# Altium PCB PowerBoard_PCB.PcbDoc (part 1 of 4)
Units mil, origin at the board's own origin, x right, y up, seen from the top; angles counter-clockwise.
Board outline 9251.97 x 3346.46 mil, 6 copper layers (Top Layer, Signal Layer 1, Signal Layer 2, Signal Layer 3, Signal Layer 4, Bottom Layer), stack 65.8 mil thick; 241 components, 145 nets, 894 pads, 120 vias.
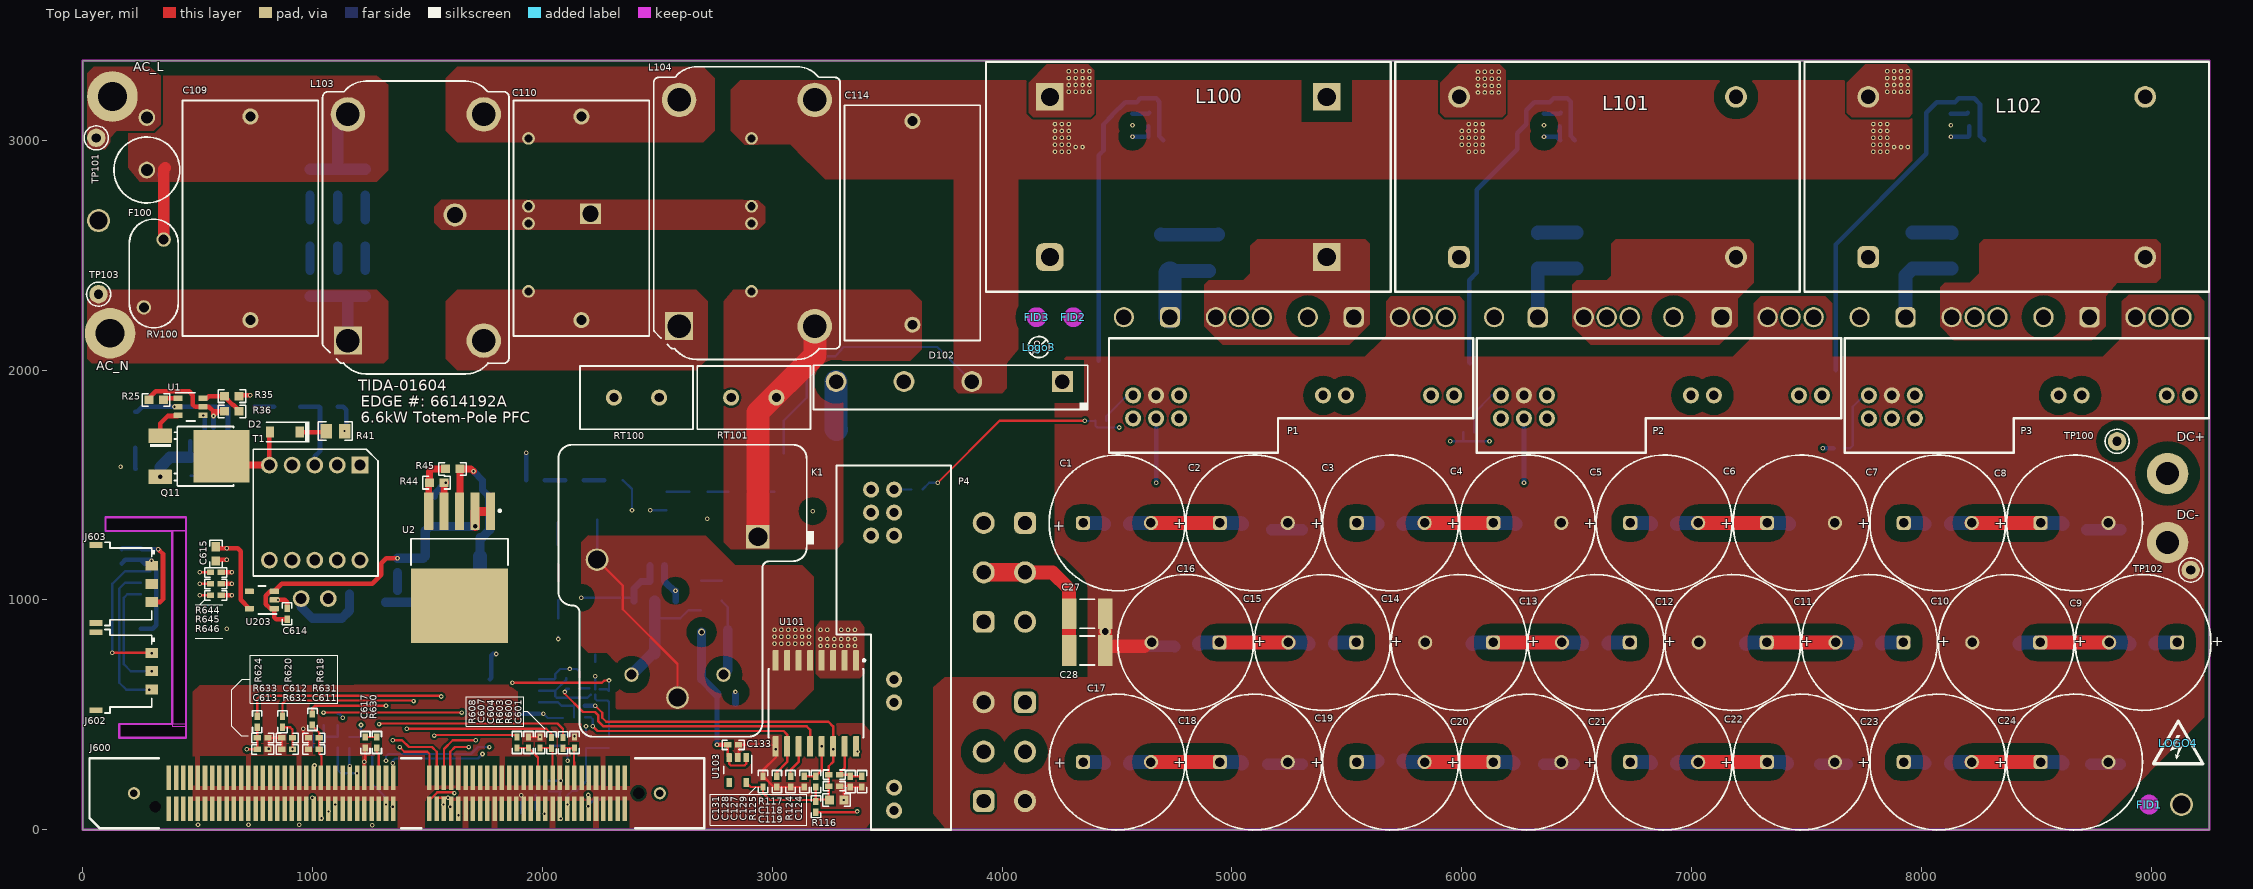
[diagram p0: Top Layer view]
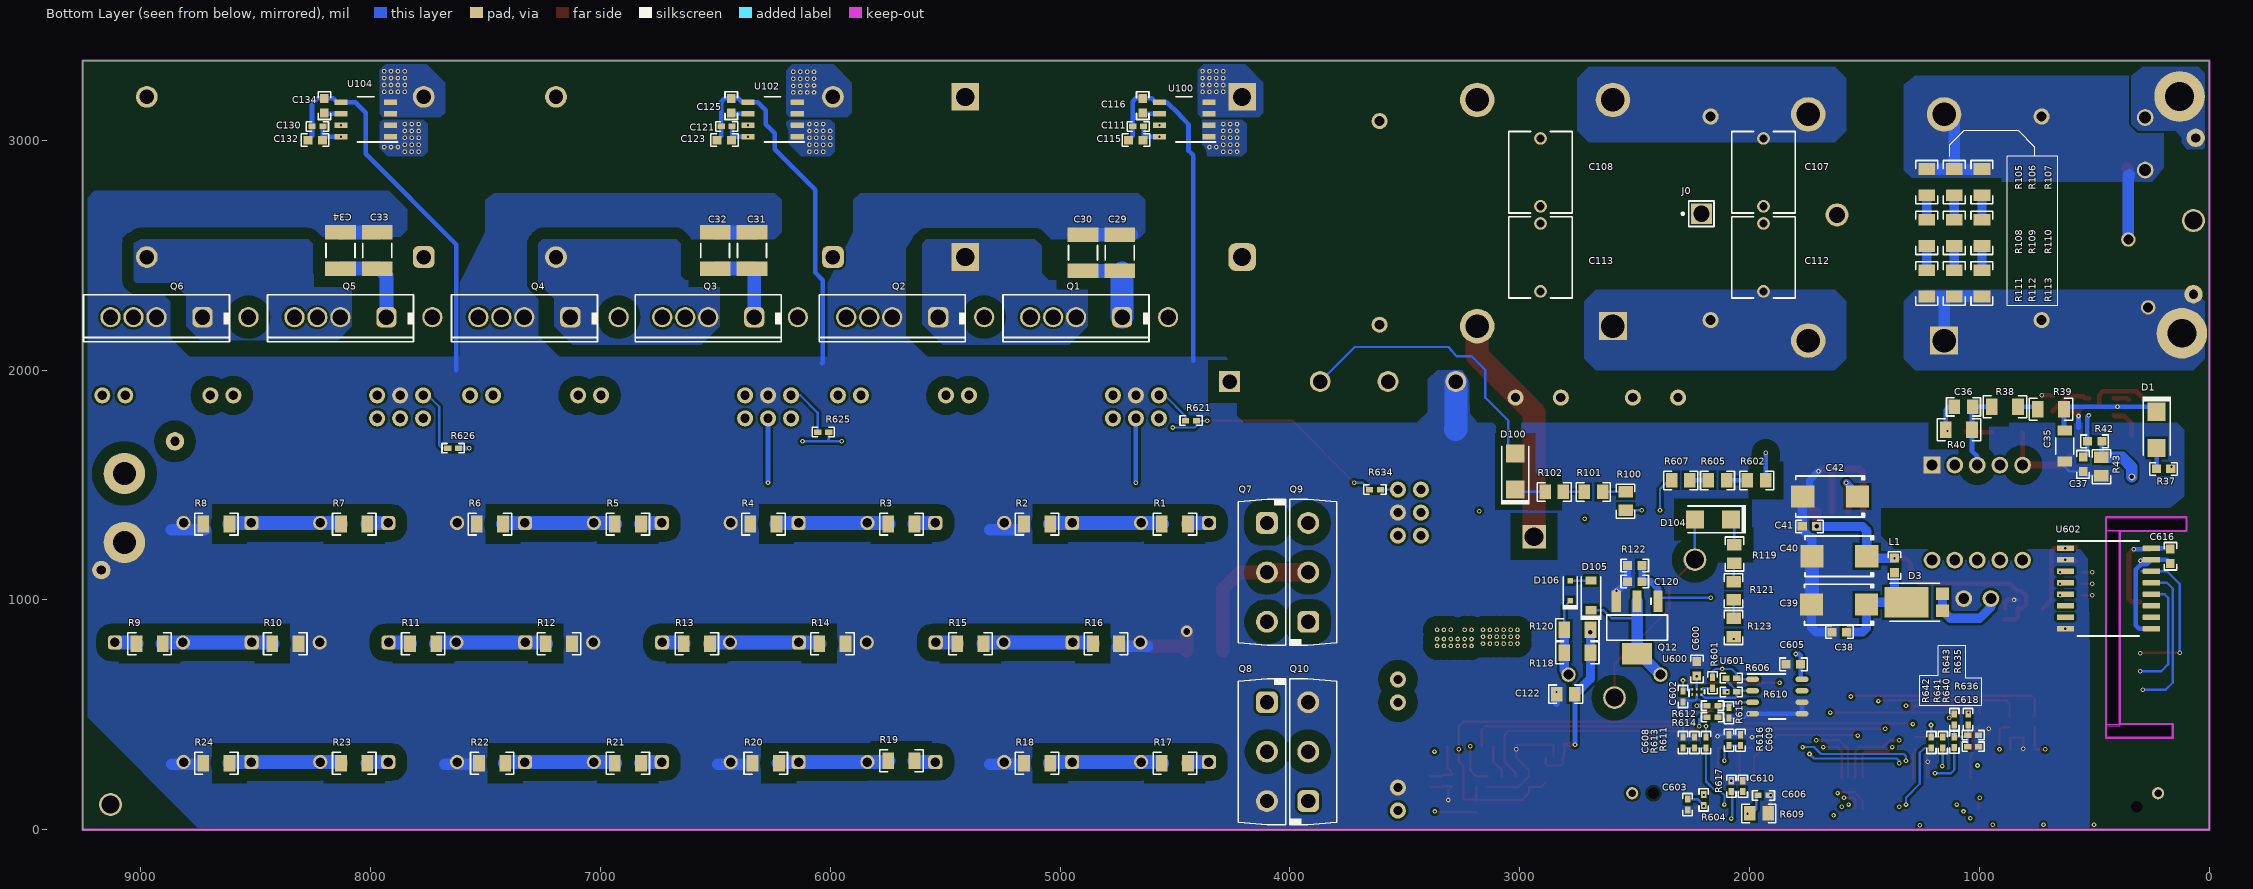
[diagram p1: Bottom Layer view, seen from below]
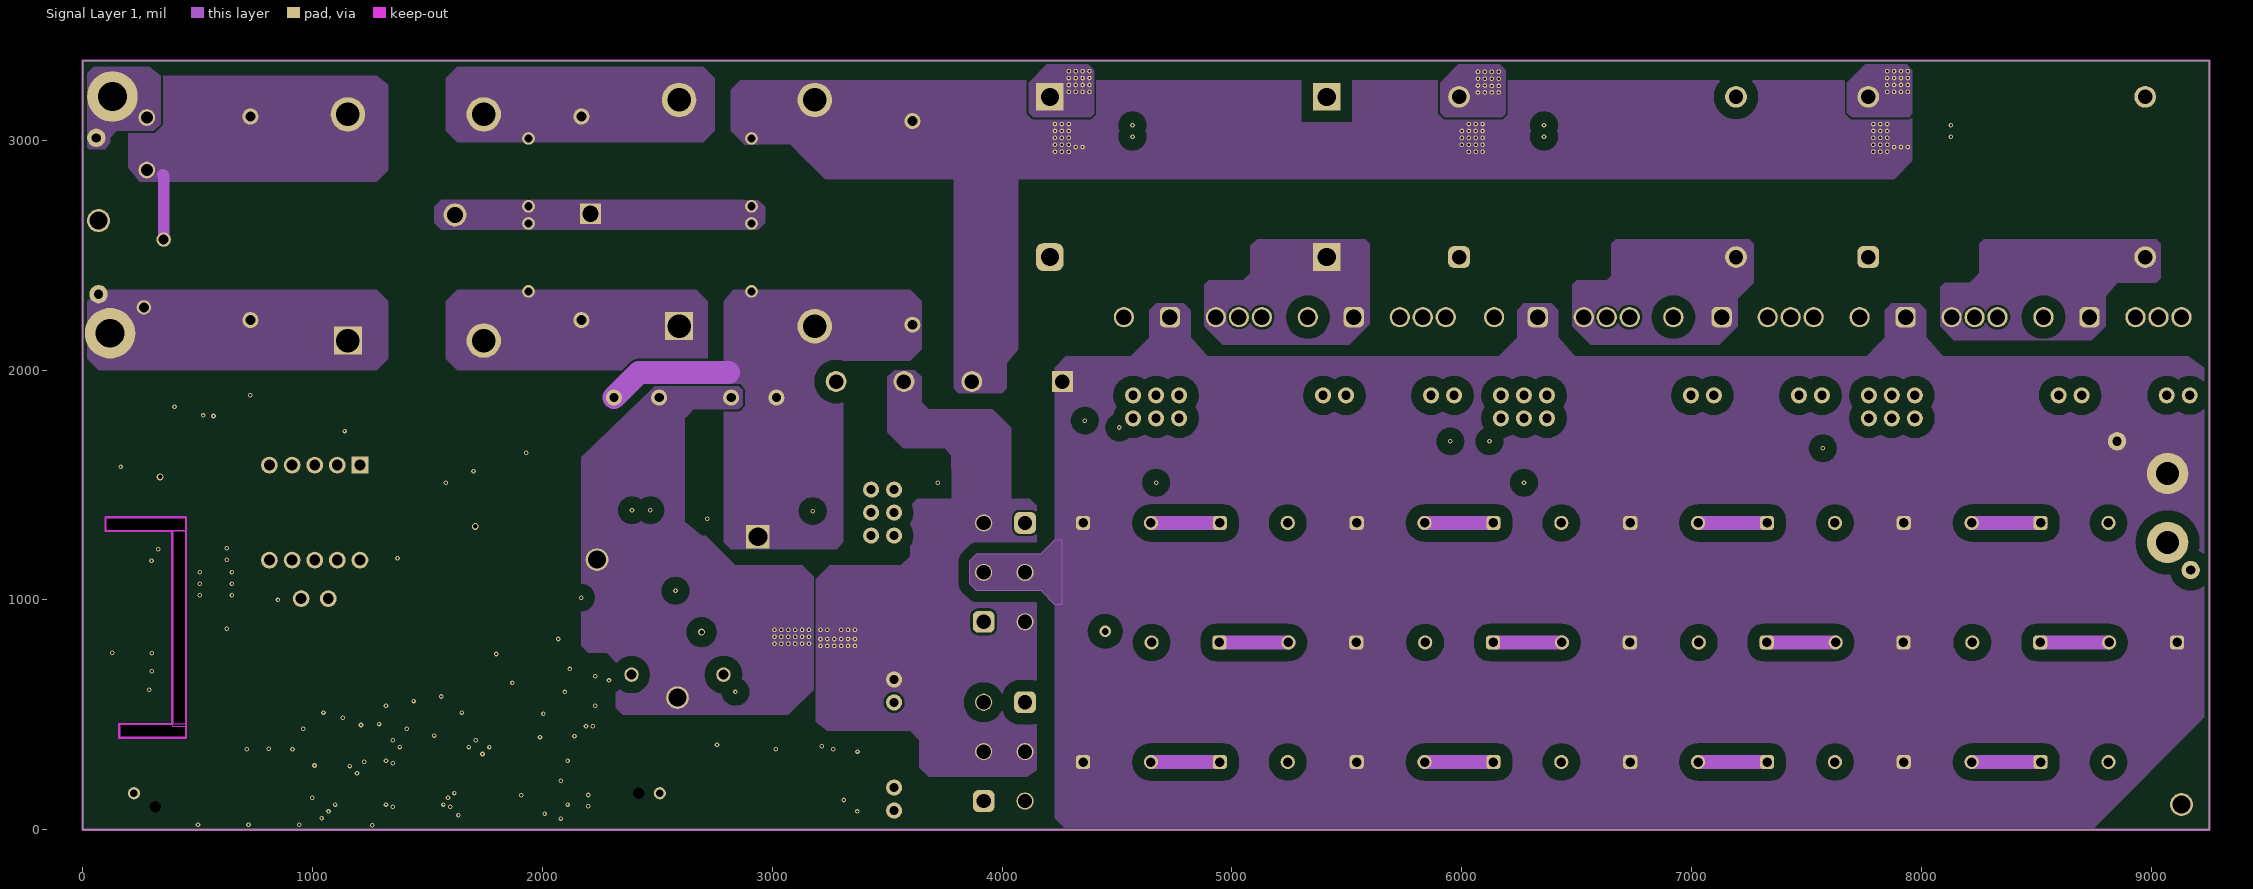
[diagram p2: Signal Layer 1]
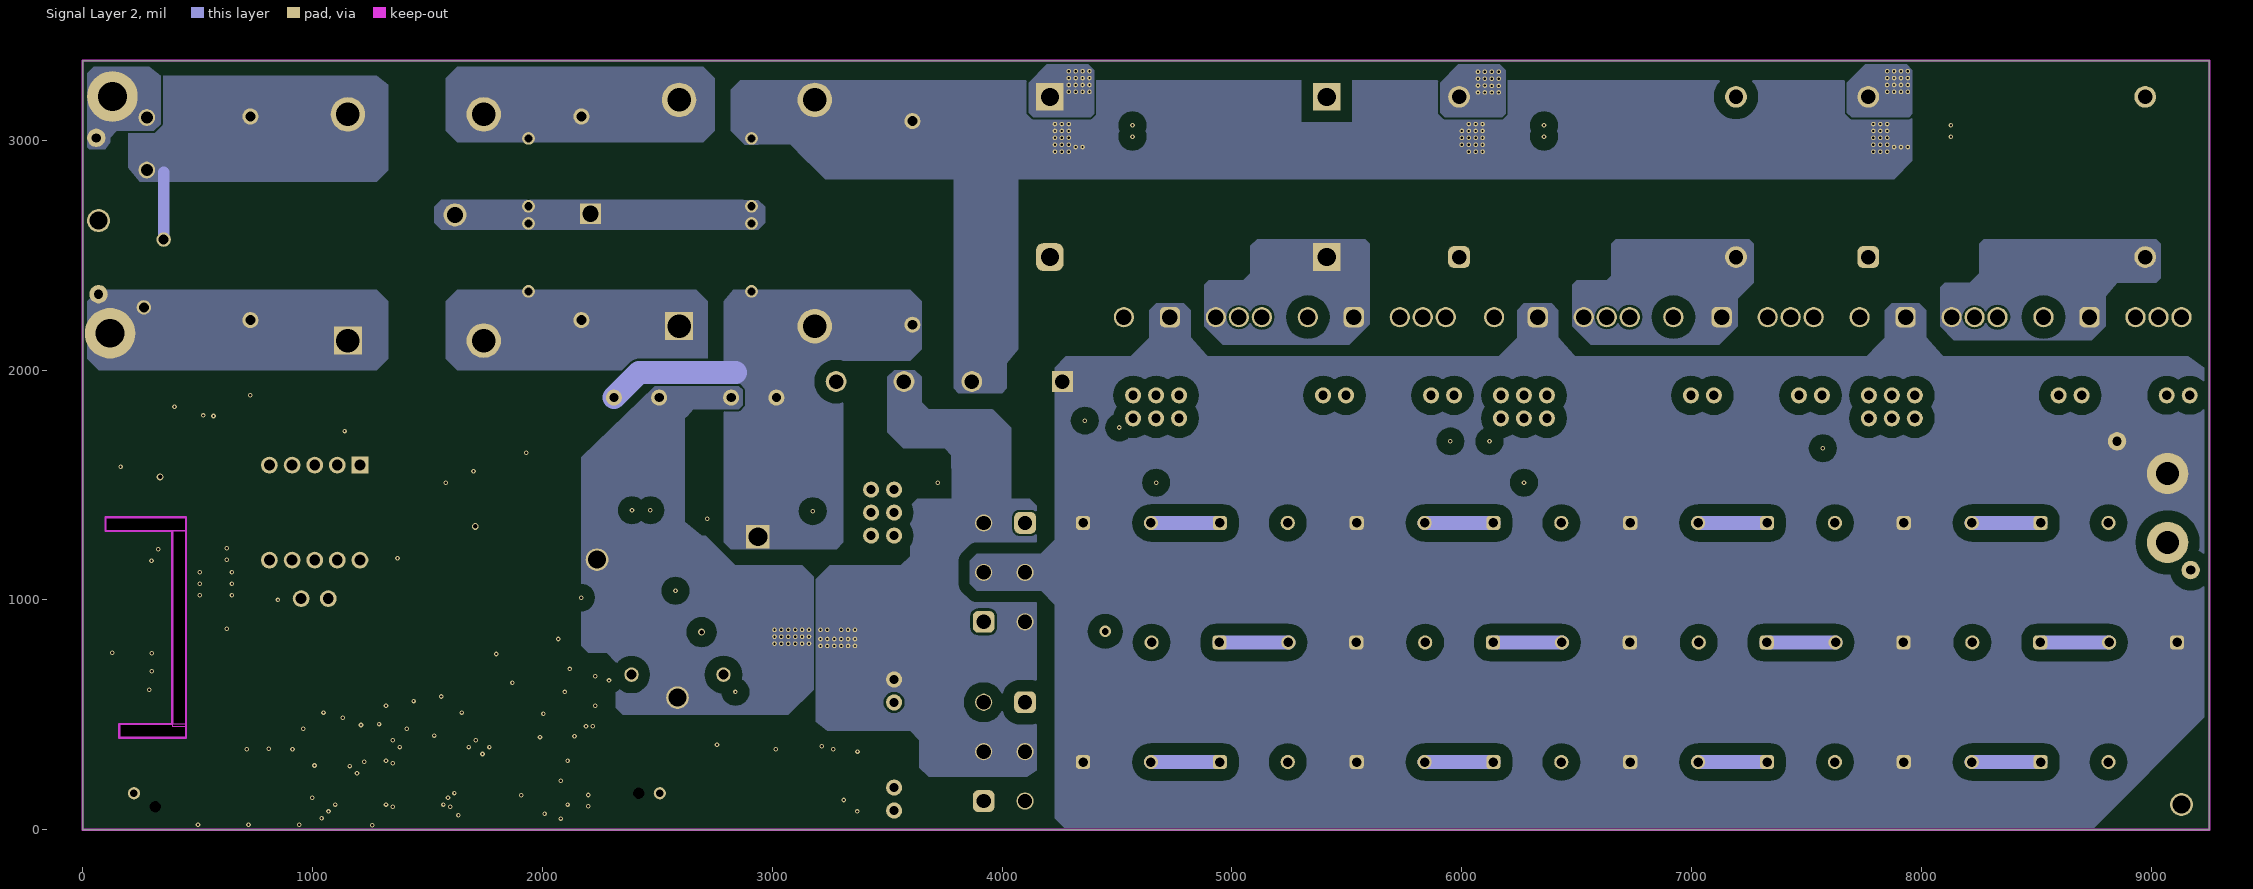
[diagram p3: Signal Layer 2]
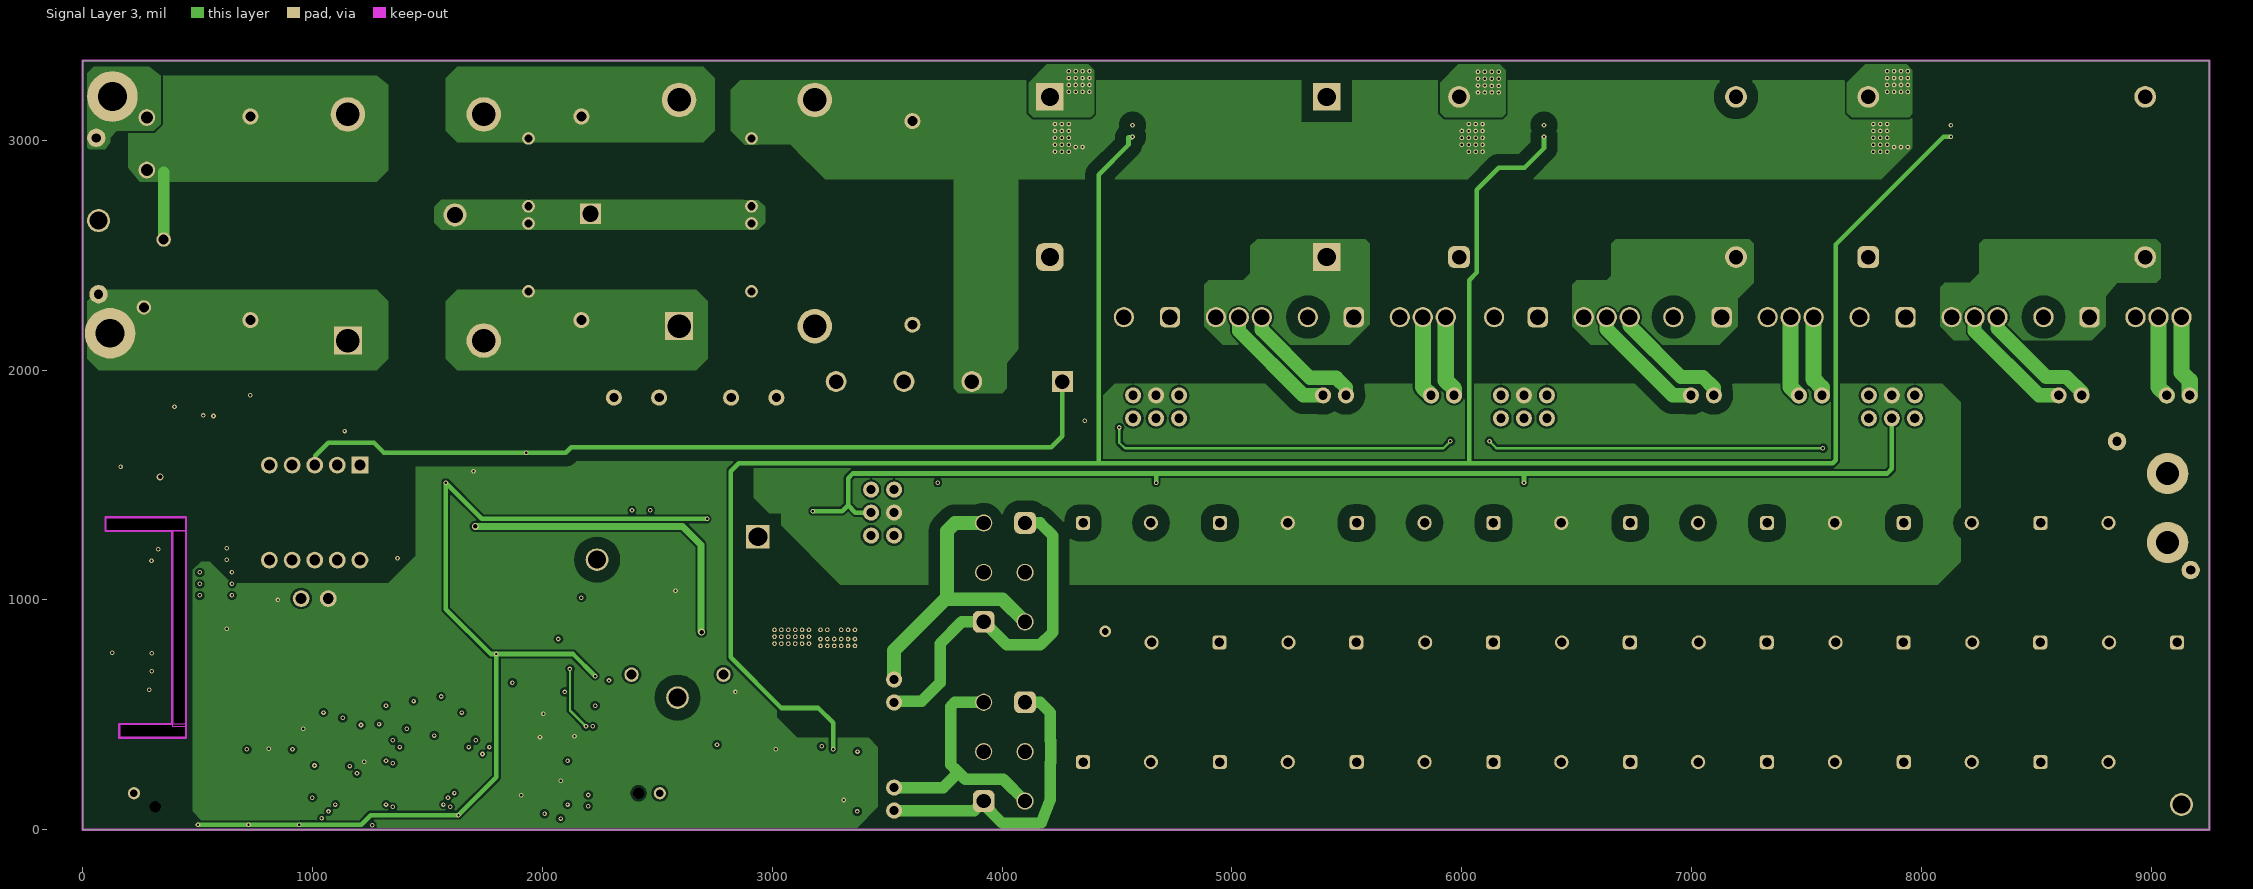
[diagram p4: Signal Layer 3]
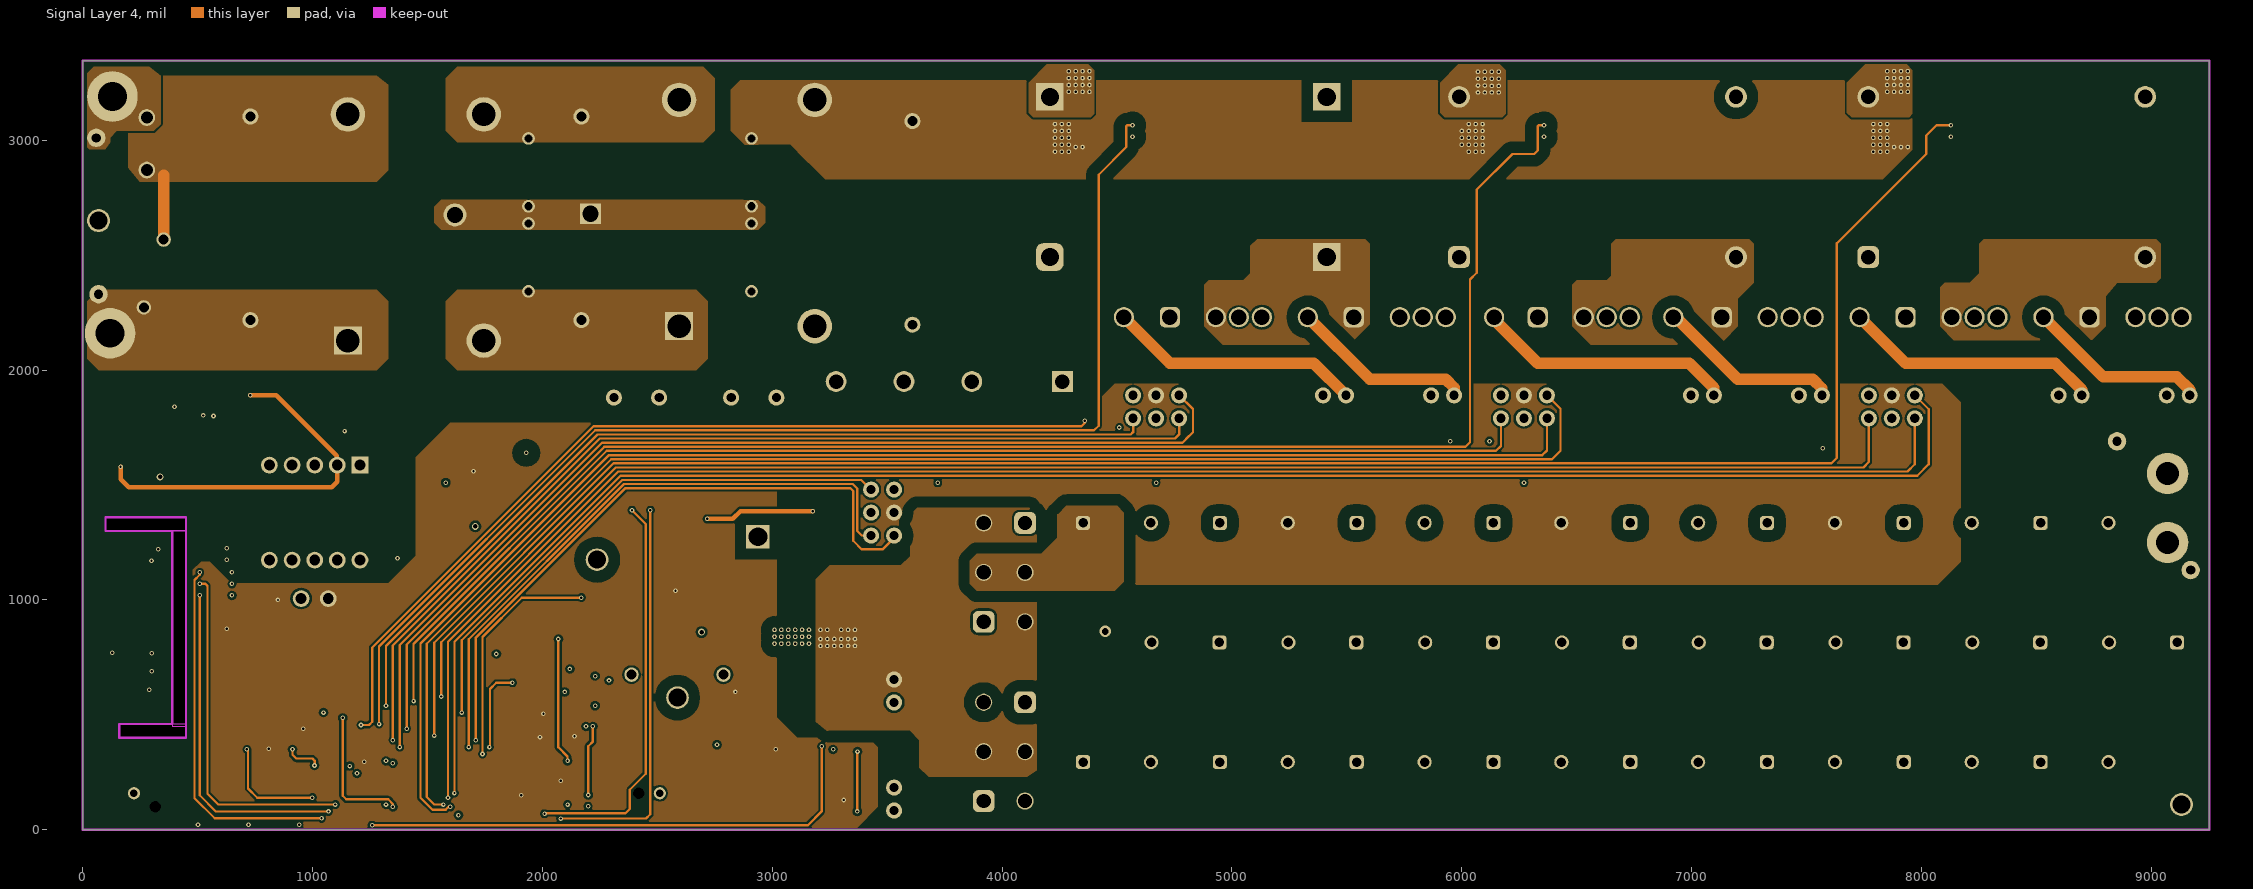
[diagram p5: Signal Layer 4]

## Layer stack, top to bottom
Top Solder: solder mask 0.4, Solder Resist, Dk 3.5
Top Layer: signal copper 2.8
Dielectric1: prepreg 7, Dk 4.2
Signal Layer 1: signal copper 2.8
Dielectric 3: core 14, FR-4, Dk 4.2
Signal Layer 2: signal copper 2.8
Dielectric 2: prepreg 7, Dk 4.2
Signal Layer 3: signal copper 2.8
Dielectric 4: prepreg 7, Dk 4.2
Signal Layer 4: signal copper 2.8
Dielectric 5: core 14, FR-4, Dk 4.2
Bottom Layer: signal copper 2.8
Bottom Solder: solder mask 0.4, Solder Resist, Dk 3.5

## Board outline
0,0 9251.97,0 9251.97,3346.46 0,3346.46
cut-out: 100,1300 450,1300 450,1360 100,1360
cut-out: 160,400 450,400 450,460 160,460
cut-out: 390,450 450,450 450,1300 390,1300

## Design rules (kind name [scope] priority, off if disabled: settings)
AcuteAngle [All] p1: minimum=4.50000000000000E+0001 checktracksonly=FALSE
AssemblyTestPointUsage [All] p1: valid=2
Clearance Clearance_3 [InNet('EARTH') vs Not InNet('EARTH') And Not InNet('12VS')] p1: gap=200 ignorepadtopadclearanceinfootprint=FALSE except(0: Arc-Hole Track-Hole SMDPad-Hole THPad-Hole Via-Hole Fill-Hole Poly-Hole Region-Hole Text-Hole)
Clearance Clearance_7 [InNetClass('EARTH') vs Not InNetClass('EARTH')] p2: gap=240 ignorepadtopadclearanceinfootprint=FALSE
Clearance Clearance_1 [InNetClass('HV') vs InNetClass('MV')] p3: gap=25 ignorepadtopadclearanceinfootprint=FALSE except(0: Arc-Hole Track-Hole SMDPad-Hole THPad-Hole Via-Hole Fill-Hole Poly-Hole Region-Hole Text-Hole)
Clearance Clearance_4 [InNet('PFC_4H_S') vs InNet('HVBUS')] p4: gap=50 ignorepadtopadclearanceinfootprint=FALSE except(0: Arc-Hole Track-Hole SMDPad-Hole THPad-Hole Via-Hole Fill-Hole Poly-Hole Region-Hole Text-Hole)
Clearance Clearance_2 [InNetClass('HV') vs Not InNetClass('HV') and not InComponent('T1')] p5: gap=50 ignorepadtopadclearanceinfootprint=FALSE
Clearance Clearance_6 [InNetClass('MD') vs InNet('PFC_3H_S')  Or  InNet('PFC_2H_S')  Or InNet('PFC_1H_S')] p6: gap=7.87 ignorepadtopadclearanceinfootprint=FALSE
Clearance Clearance_5 [InNetClass('MD') vs Not InNetClass('MD')] p7: gap=50 ignorepadtopadclearanceinfootprint=FALSE except(0: Arc-Hole Track-Hole SMDPad-Hole THPad-Hole Via-Hole Fill-Hole Poly-Hole Region-Hole Text-Hole)
Clearance Clearance_Keepouts [((IsTrack Or IsArc) And Not InPoly) And IsFree and IsKeepOut vs ((IsTrack Or IsArc) And Not InPoly) And IsFree and IsKeepOut] p8: gap=0 ignorepadtopadclearanceinfootprint=FALSE
Clearance Clearance_BoardEdge_MountingHoles [OnCopper and InComponentClass('Mounting Holes') vs IsKeepOut] p9: gap=40 ignorepadtopadclearanceinfootprint=FALSE except(0: Arc-Hole Track-Hole SMDPad-Hole THPad-Hole Via-Hole Fill-Hole Poly-Hole Region-Hole Text-Hole)
Clearance Clearance_BoardEdge_Poly [OnCopper and InPoly vs IsKeepOut] p10: gap=25 ignorepadtopadclearanceinfootprint=FALSE except(0: Arc-Hole Track-Hole SMDPad-Hole THPad-Hole Via-Hole Fill-Hole Poly-Hole Region-Hole Text-Hole)
Clearance Clearance_BoardEdge [OnCopper and Not InComponentClass('Logo') and not InComponentClass('FiducialMark') and not InRegion(1000,500,4000,800) and Not IsKeepout vs IsKeepOut] p11: gap=25 ignorepadtopadclearanceinfootprint=FALSE
Clearance Clearance_Poly [InPolygon] p12: gap=10 ignorepadtopadclearanceinfootprint=FALSE
Clearance Clearance_FID [IsKeepOut and InComponentClass('FiducialMark') vs IsPad and InComponentClass('FiducialMark')] p13: gap=0 ignorepadtopadclearanceinfootprint=FALSE
Clearance [All] p14: gap=7.87 ignorepadtopadclearanceinfootprint=FALSE
ComponentClearance ComponentClearance_Ycap [InComponent('C108')or InComponent('C113') or InComponent('C112')or InComponent('C107') vs InComponent('L104')or InComponent('C110')] p1: gap=0 collisioncheckmode=3 verticalgap=0 showdistances=TRUE
ComponentClearance ComponentClearance_Bulkycap [HasFootprint('BXW_1450x4500') vs HasFootprint('BXW_1450x4500')] p2: gap=0 collisioncheckmode=3 verticalgap=0 showdistances=TRUE
ComponentClearance ComponentClearance_MountingHoles_FiducialMarks [InComponentClass('Mounting Holes') vs InComponentClass('FiducialMark')] p3: gap=20 collisioncheckmode=3 verticalgap=10 showdistances=FALSE
ComponentClearance ComponentClearance_Shunt [InComponentClass('Header') vs InComponentClass('Shunt')] p4: gap=0 collisioncheckmode=3 verticalgap=0 showdistances=FALSE
ComponentClearance ComponentClearance_Logo [InComponentClass('Logo')] p5: gap=5 collisioncheckmode=3 verticalgap=10 showdistances=FALSE
ComponentClearance ComponentClearance_ScrewToNut [(HasFootprint('NY PMS 440 0025 PH')) vs (HasFootprint('Keystone_1902C'))] p6: gap=20 collisioncheckmode=3 verticalgap=100000 showdistances=FALSE
ComponentClearance ComponentClearance_MountingHoles [InComponentClass('Mounting Holes')] p7: gap=20 collisioncheckmode=3 verticalgap=10 showdistances=FALSE
ComponentClearance ComponentClearance_SmallPassives [HasFootprint('0201*') or HasFootprint('0402*') or HasFootprint('0508') or HasFootprint('0603*') or HasFootprint('0612') or HasFootprint('0805*') or HasFootprint('0815*') or HasFootprint('0830*') or HasFootprint('1206*') or HasFootprint('1210*') or HasFootprint('1808*') or HasFootprint('1812*') or HasFootprint('1825*') or HasFootprint('2010*') or HasFootprint('2220*') or HasFootprint('2225*') or HasFootprint('2512*') or HasFootprint('2728*') or HasFootprint('3518*') vs HasFootprint('0201*') or HasFootprint('0402*') or HasFootprint('0508') or HasFootprint('0603*') or HasFootprint('0612') or HasFootprint('0805*') or HasFootprint('0815*') or HasFootprint('0830*') or HasFootprint('1206*') or HasFootprint('1210*') or HasFootprint('1808*') or HasFootprint('1812*') or HasFootprint('1825*') or HasFootprint('2010*') or HasFootprint('2220*') or HasFootprint('2225*') or HasFootprint('2512*') or HasFootprint('2728*') or HasFootprint('3518*')] p8: gap=20 collisioncheckmode=3 verticalgap=20 showdistances=FALSE
ComponentClearance ComponentClearance_THtoSMT [IsThruComponent vs IsSMTComponent] p9: gap=10 collisioncheckmode=3 verticalgap=10 showdistances=FALSE
ComponentClearance ComponentClearance_THtoTH [IsThruComponent vs IsThruComponent] p10: gap=10 collisioncheckmode=3 verticalgap=10 showdistances=FALSE
ComponentClearance [All] p11: gap=10 collisioncheckmode=3 verticalgap=10 showdistances=FALSE
DiffPairsRouting [All] p1: maxlimit=100 minlimit=10 mostfreqgap=10 toplayer_minwidth=15 toplayer_maxwidth=15 toplayer_prefwidth=15 midlayer1_minwidth=15 midlayer1_maxwidth=15 midlayer1_prefwidth=15 midlayer2_minwidth=15 midlayer2_maxwidth=15 midlayer2_prefwidth=15 midlayer3_minwidth=15 midlayer3_maxwidth=15 midlayer3_prefwidth=15 midlayer4_minwidth=15 midlayer4_maxwidth=15 midlayer4_prefwidth=15 bottomlayer_minwidth=15 bottomlayer_maxwidth=15 bottomlayer_prefwidth=15 maxuncoupledlength=1000
FabricationTestPointUsage TestPointUsage [All] p1: valid=2 allowmultiple=FALSE
FabricationTestpoint Testpoint [All] p1: side=3 testpointundercomponent=TRUE minsize=40 maxsize=100 preferedsize=60 minholesize=0 maxholesize=40 preferedholesize=32 testpointgrid=1 allowsidetop=TRUE allowsidebottom=TRUE usegrid=TRUE gridtolerance=0.01
FanoutControl Fanout_LCC [IsLCC] p1: bgadir=Out bgaviamode=Centered fanoutstyle=Auto fanoutdirection=Alternating viagrid=1 // Fanout_LCC (Default Rule)
FanoutControl Fanout_BGA [IsBGA] p2: bgadir=Out bgaviamode=Centered fanoutstyle=Auto fanoutdirection=Alternating viagrid=1 // Fanout_BGA (Default Rule)
FanoutControl Fanout_Default [All] p4: bgadir=Out bgaviamode=Centered fanoutstyle=Auto fanoutdirection=Alternating viagrid=1 // Fanout_Default (Default Rule)
FanoutControl Fanout_Small [(CompPinCount < 5)] p5: bgadir=Out bgaviamode=Centered fanoutstyle=Auto fanoutdirection=OutThenIn viagrid=1 // Fanout_Small (Default Rule)
Height [All] p1: minheight=0 maxheight=3000 prefheight=500
HoleSize [All] p1: absolutevalues=TRUE maxlimit=251 minlimit=7 maxpercent=80.000 minpercent=20.000
MinimumAnnularRing MinimumAnnularRing_ThermalPadVias [IsVia and InAnyComponent] p1: minimumring=5.91
MinimumAnnularRing [All] p2: minimumring=4.9
MinimumSolderMaskSliver MinimumSolderMaskSliver_Logo [InComponentClass('Logo') vs InComponentClass('Logo')] p1: minsoldermaskwidth=0.7
MinimumSolderMaskSliver [All] p2: minsoldermaskwidth=2
PlaneConnect [All] p1: planeconnectstyle=Direct reliefexpansion=10 reliefentries=4 reliefconductorwidth=10 reliefairgap=10
PolygonConnect PolygonConnect_26 [All vs IsNamedPolygon('12VP') Or  IsNamedPolygon('D106_1') Or  IsNamedPolygon('HVBUS') Or  IsNamedPolygon('Earth') Or  IsNamedPolygon('L101_1') Or  IsNamedPolygon('C110_2') Or  IsNamedPolygon('Earth') Or  IsNamedPolygon('SWNODE3') Or  IsNamedPolygon('C107_1') Or  IsNamedPolygon('L102_1') Or  IsNamedPolygon('L100_1') Or  IsNamedPolygon('AC_N') Or  IsNamedPolygon('C109_1') Or  IsNamedPolygon('Earth') Or  IsNamedPolygon('C109_1') Or  IsNamedPolygon('F100_2') Or  IsNamedPolygon('-BRDG_N') Or  IsNamedPolygon('C109_1') Or  IsNamedPolygon('-BRDG_N') Or  IsNamedPolygon('Earth') Or  IsNamedPolygon('C113_2') Or  IsNamedPolygon('Earth') Or  IsNamedPolygon('C110_2') Or  IsNamedPolygon('C107_1') Or  IsNamedPolygon('SWNODE2') Or  IsNamedPolygon('SGND2') Or  IsNamedPolygon('C113_2') Or  IsNamedPolygon('C109_2') Or  IsNamedPolygon('L101_1') Or  IsNamedPolygon('AC_N') Or  IsNamedPolygon('C113_2') Or  IsNamedPolygon('SWNODE2') Or  IsNamedPolygon('-BRDG_N') Or  IsNamedPolygon('C113_2') Or  IsNamedPolygon('AC_N') Or  IsNamedPolygon('5VS') Or  IsNamedPolygon('C110_2') Or  IsNamedPolygon('PGND') Or  IsNamedPolygon('HVBUS') Or  IsNamedPolygon('C107_1') Or  IsNamedPolygon('F100_2') Or  IsNamedPolygon('AC_L') Or  IsNamedPolygon('SGND2') Or  IsNamedPolygon('-BRDG_N') Or  IsNamedPolygon('C109_1') Or  IsNamedPolygon('L101_1') Or  IsNamedPolygon('C109_2') Or  IsNamedPolygon('C110_2') Or  IsNamedPolygon('C109_2') Or  IsNamedPolygon('-BRDG_N') Or  IsNamedPolygon('C110_2') Or  IsNamedPolygon('C109_1') Or  IsNamedPolygon('C109_2') Or  IsNamedPolygon('F100_2') Or  IsNamedPolygon('AC_N') Or  IsNamedPolygon('C109_2') Or  IsNamedPolygon('F100_2') Or  IsNamedPolygon('C107_1') Or  IsNamedPolygon('C113_2') Or  IsNamedPolygon('F100_2') Or  IsNamedPolygon('AC_N') Or  IsNamedPolygon('C110_2') Or  IsNamedPolygon('SWNODE1') Or  IsNamedPolygon('C109_2') Or  IsNamedPolygon('C109_1') Or  IsNamedPolygon('C107_1') Or  IsNamedPolygon('F100_2') Or  IsNamedPolygon('C107_1') Or  IsNamedPolygon('AC_N') Or  IsNamedPolygon('L100_1') Or  IsNamedPolygon('Earth') Or  IsNamedPolygon('C113_2') Or  IsNamedPolygon('SWNODE1') Or  IsNamedPolygon('AC_L') Or  IsNamedPolygon('L102_1') Or  IsNamedPolygon('SWNODE3') Or  IsNamedPolygon('AC_L')] p1: connectstyle=Direct reliefconductorwidth=10 reliefentries=4 polygonreliefangle="90 Angle" airgapwidth=10
PolygonConnect PolygonConnect_25 [All vs IsNamedPolygon('12VP') Or  IsNamedPolygon('SWNODE2') Or  IsNamedPolygon('F100_2') Or  IsNamedPolygon('AC_N') Or  IsNamedPolygon('C113_2') Or  IsNamedPolygon('-BRDG_N') Or  IsNamedPolygon('L102_1') Or  IsNamedPolygon('Earth') Or  IsNamedPolygon('SWNODE3') Or  IsNamedPolygon('L101_1') Or  IsNamedPolygon('C109_2') Or  IsNamedPolygon('C107_1') Or  IsNamedPolygon('C110_2') Or  IsNamedPolygon('C109_2') Or  IsNamedPolygon('C110_2') Or  IsNamedPolygon('5VS') Or  IsNamedPolygon('L101_1') Or  IsNamedPolygon('-BRDG_N') Or  IsNamedPolygon('AC_L') Or  IsNamedPolygon('AC_N') Or  IsNamedPolygon('F100_2') Or  IsNamedPolygon('AC_N') Or  IsNamedPolygon('-BRDG_N') Or  IsNamedPolygon('AC_L') Or  IsNamedPolygon('L102_1') Or  IsNamedPolygon('C109_2') Or  IsNamedPolygon('L100_1') Or  IsNamedPolygon('C113_2') Or  IsNamedPolygon('C113_2') Or  IsNamedPolygon('C113_2') Or  IsNamedPolygon('C109_2') Or  IsNamedPolygon('Earth') Or  IsNamedPolygon('AC_N') Or  IsNamedPolygon('C107_1') Or  IsNamedPolygon('C107_1') Or  IsNamedPolygon('F100_2') Or  IsNamedPolygon('C109_1') Or  IsNamedPolygon('-BRDG_N') Or  IsNamedPolygon('C110_2') Or  IsNamedPolygon('AC_L') Or  IsNamedPolygon('C113_2') Or  IsNamedPolygon('Earth') Or  IsNamedPolygon('C109_1') Or  IsNamedPolygon('C110_2') Or  IsNamedPolygon('SWNODE3') Or  IsNamedPolygon('C109_1') Or  IsNamedPolygon('C109_2') Or  IsNamedPolygon('C107_1') Or  IsNamedPolygon('F100_2') Or  IsNamedPolygon('D106_1') Or  IsNamedPolygon('C109_1') Or  IsNamedPolygon('L101_1') Or  IsNamedPolygon('C110_2') Or  IsNamedPolygon('C107_1') Or  IsNamedPolygon('C109_2') Or  IsNamedPolygon('C109_1') Or  IsNamedPolygon('Earth') Or  IsNamedPolygon('HVBUS') Or  IsNamedPolygon('Earth') Or  IsNamedPolygon('AC_N') Or  IsNamedPolygon('SWNODE2') Or  IsNamedPolygon('AC_N') Or  IsNamedPolygon('Earth') Or  IsNamedPolygon('F100_2') Or  IsNamedPolygon('C110_2') Or  IsNamedPolygon('F100_2') Or  IsNamedPolygon('SWNODE1') Or  IsNamedPolygon('C113_2') Or  IsNamedPolygon('C107_1') Or  IsNamedPolygon('C109_1') Or  IsNamedPolygon('L100_1') Or  IsNamedPolygon('-BRDG_N') Or  IsNamedPolygon('SWNODE1')] p2: connectstyle=Direct reliefconductorwidth=10 reliefentries=4 polygonreliefangle="90 Angle" airgapwidth=10
PolygonConnect PolygonConnect_24 [All vs IsNamedPolygon('12VP') Or  IsNamedPolygon('C113_2') Or  IsNamedPolygon('C107_1') Or  IsNamedPolygon('L100_1') Or  IsNamedPolygon('C107_1') Or  IsNamedPolygon('C107_1') Or  IsNamedPolygon('5VS') Or  IsNamedPolygon('C113_2') Or  IsNamedPolygon('SWNODE3') Or  IsNamedPolygon('AC_N') Or  IsNamedPolygon('C113_2') Or  IsNamedPolygon('C113_2') Or  IsNamedPolygon('C109_2') Or  IsNamedPolygon('F100_2') Or  IsNamedPolygon('F100_2') Or  IsNamedPolygon('C113_2') Or  IsNamedPolygon('Earth') Or  IsNamedPolygon('C109_2') Or  IsNamedPolygon('C109_1') Or  IsNamedPolygon('C110_2') Or  IsNamedPolygon('-BRDG_N') Or  IsNamedPolygon('AC_N') Or  IsNamedPolygon('C110_2') Or  IsNamedPolygon('L102_1') Or  IsNamedPolygon('AC_N') Or  IsNamedPolygon('D106_1') Or  IsNamedPolygon('L102_1') Or  IsNamedPolygon('Earth') Or  IsNamedPolygon('F100_2') Or  IsNamedPolygon('-BRDG_N') Or  IsNamedPolygon('C109_1') Or  IsNamedPolygon('SWNODE2') Or  IsNamedPolygon('C109_2') Or  IsNamedPolygon('SWNODE1') Or  IsNamedPolygon('-BRDG_N') Or  IsNamedPolygon('-BRDG_N') Or  IsNamedPolygon('-BRDG_N') Or  IsNamedPolygon('AC_N') Or  IsNamedPolygon('AC_L') Or  IsNamedPolygon('AC_L') Or  IsNamedPolygon('SWNODE3') Or  IsNamedPolygon('C113_2') Or  IsNamedPolygon('C109_1') Or  IsNamedPolygon('C109_2') Or  IsNamedPolygon('Earth') Or  IsNamedPolygon('SWNODE1') Or  IsNamedPolygon('C110_2') Or  IsNamedPolygon('SWNODE2') Or  IsNamedPolygon('F100_2') Or  IsNamedPolygon('C107_1') Or  IsNamedPolygon('F100_2') Or  IsNamedPolygon('L100_1') Or  IsNamedPolygon('C107_1') Or  IsNamedPolygon('C110_2') Or  IsNamedPolygon('L101_1') Or  IsNamedPolygon('C110_2') Or  IsNamedPolygon('AC_N') Or  IsNamedPolygon('C110_2') Or  IsNamedPolygon('Earth') Or  IsNamedPolygon('AC_N') Or  IsNamedPolygon('C109_2') Or  IsNamedPolygon('Earth') Or  IsNamedPolygon('C109_2') Or  IsNamedPolygon('C109_1') Or  IsNamedPolygon('C109_1') Or  IsNamedPolygon('C109_1') Or  IsNamedPolygon('C107_1') Or  IsNamedPolygon('L101_1') Or  IsNamedPolygon('L101_1') Or  IsNamedPolygon('F100_2') Or  IsNamedPolygon('Earth')] p3: connectstyle=Direct reliefconductorwidth=10 reliefentries=4 polygonreliefangle="90 Angle" airgapwidth=10
PolygonConnect PolygonConnect_23 [All vs IsNamedPolygon('C110_2') Or  IsNamedPolygon('C110_2') Or  IsNamedPolygon('C109_2') Or  IsNamedPolygon('C110_2') Or  IsNamedPolygon('C110_2') Or  IsNamedPolygon('C110_2') Or  IsNamedPolygon('C109_2') Or  IsNamedPolygon('12VP') Or  IsNamedPolygon('5VS') Or  IsNamedPolygon('D106_1') Or  IsNamedPolygon('C109_2') Or  IsNamedPolygon('C109_2') Or  IsNamedPolygon('C109_2') Or  IsNamedPolygon('C109_2') Or  IsNamedPolygon('C109_1') Or  IsNamedPolygon('F100_2') Or  IsNamedPolygon('C109_1') Or  IsNamedPolygon('Earth') Or  IsNamedPolygon('AC_N') Or  IsNamedPolygon('Earth') Or  IsNamedPolygon('F100_2') Or  IsNamedPolygon('C109_1') Or  IsNamedPolygon('Earth') Or  IsNamedPolygon('C109_1') Or  IsNamedPolygon('-BRDG_N') Or  IsNamedPolygon('C107_1') Or  IsNamedPolygon('AC_L') Or  IsNamedPolygon('C109_1') Or  IsNamedPolygon('SWNODE2') Or  IsNamedPolygon('C113_2') Or  IsNamedPolygon('SWNODE1') Or  IsNamedPolygon('-BRDG_N') Or  IsNamedPolygon('-BRDG_N') Or  IsNamedPolygon('Earth') Or  IsNamedPolygon('C107_1') Or  IsNamedPolygon('SWNODE1') Or  IsNamedPolygon('F100_2') Or  IsNamedPolygon('-BRDG_N') Or  IsNamedPolygon('C107_1') Or  IsNamedPolygon('AC_N') Or  IsNamedPolygon('AC_N') Or  IsNamedPolygon('Earth') Or  IsNamedPolygon('-BRDG_N') Or  IsNamedPolygon('C107_1') Or  IsNamedPolygon('SWNODE3') Or  IsNamedPolygon('C107_1') Or  IsNamedPolygon('C113_2') Or  IsNamedPolygon('F100_2') Or  IsNamedPolygon('SWNODE3') Or  IsNamedPolygon('Earth') Or  IsNamedPolygon('C109_1') Or  IsNamedPolygon('C113_2') Or  IsNamedPolygon('F100_2') Or  IsNamedPolygon('C113_2') Or  IsNamedPolygon('C110_2') Or  IsNamedPolygon('AC_L') Or  IsNamedPolygon('AC_N') Or  IsNamedPolygon('AC_N') Or  IsNamedPolygon('AC_N') Or  IsNamedPolygon('SWNODE2') Or  IsNamedPolygon('F100_2') Or  IsNamedPolygon('C113_2') Or  IsNamedPolygon('AC_N') Or  IsNamedPolygon('-BRDG_N') Or  IsNamedPolygon('C107_1') Or  IsNamedPolygon('C113_2')] p4: connectstyle=Direct reliefconductorwidth=10 reliefentries=4 polygonreliefangle="90 Angle" airgapwidth=10
PolygonConnect PolygonConnect_22 [All vs IsNamedPolygon('12VP') Or  IsNamedPolygon('C107_1') Or  IsNamedPolygon('C107_1') Or  IsNamedPolygon('C109_1') Or  IsNamedPolygon('Earth') Or  IsNamedPolygon('Earth') Or  IsNamedPolygon('Earth') Or  IsNamedPolygon('C109_1') Or  IsNamedPolygon('C107_1') Or  IsNamedPolygon('C109_1') Or  IsNamedPolygon('Earth') Or  IsNamedPolygon('Earth') Or  IsNamedPolygon('C109_1') Or  IsNamedPolygon('AC_L') Or  IsNamedPolygon('C107_1') Or  IsNamedPolygon('C107_1') Or  IsNamedPolygon('AC_L') Or  IsNamedPolygon('C107_1') Or  IsNamedPolygon('Earth') Or  IsNamedPolygon('AC_N') Or  IsNamedPolygon('C113_2') Or  IsNamedPolygon('C110_2') Or  IsNamedPolygon('C109_1') Or  IsNamedPolygon('F100_2') Or  IsNamedPolygon('C110_2') Or  IsNamedPolygon('C113_2') Or  IsNamedPolygon('AC_N') Or  IsNamedPolygon('-BRDG_N') Or  IsNamedPolygon('AC_N') Or  IsNamedPolygon('F100_2') Or  IsNamedPolygon('C110_2') Or  IsNamedPolygon('F100_2') Or  IsNamedPolygon('-BRDG_N') Or  IsNamedPolygon('C113_2') Or  IsNamedPolygon('C110_2') Or  IsNamedPolygon('-BRDG_N') Or  IsNamedPolygon('AC_N') Or  IsNamedPolygon('C113_2') Or  IsNamedPolygon('F100_2') Or  IsNamedPolygon('F100_2') Or  IsNamedPolygon('F100_2') Or  IsNamedPolygon('AC_N') Or  IsNamedPolygon('C110_2') Or  IsNamedPolygon('AC_N') Or  IsNamedPolygon('-BRDG_N') Or  IsNamedPolygon('AC_N') Or  IsNamedPolygon('-BRDG_N') Or  IsNamedPolygon('-BRDG_N') Or  IsNamedPolygon('C109_1') Or  IsNamedPolygon('C113_2') Or  IsNamedPolygon('C113_2') Or  IsNamedPolygon('C109_2') Or  IsNamedPolygon('C109_2') Or  IsNamedPolygon('C109_2') Or  IsNamedPolygon('5VS') Or  IsNamedPolygon('C110_2') Or  IsNamedPolygon('D106_1') Or  IsNamedPolygon('C109_2') Or  IsNamedPolygon('C109_2') Or  IsNamedPolygon('C109_2')] p5: connectstyle=Direct reliefconductorwidth=10 reliefentries=4 polygonreliefangle="90 Angle" airgapwidth=10
PolygonConnect PolygonConnect_21 [All vs IsNamedPolygon('C110_2') Or  IsNamedPolygon('C113_2') Or  IsNamedPolygon('C113_2') Or  IsNamedPolygon('C113_2') Or  IsNamedPolygon('C110_2') Or  IsNamedPolygon('C109_2') Or  IsNamedPolygon('C109_2') Or  IsNamedPolygon('C110_2') Or  IsNamedPolygon('D106_1') Or  IsNamedPolygon('C110_2') Or  IsNamedPolygon('C109_2') Or  IsNamedPolygon('C113_2') Or  IsNamedPolygon('C109_2') Or  IsNamedPolygon('5VS') Or  IsNamedPolygon('C109_2') Or  IsNamedPolygon('C110_2') Or  IsNamedPolygon('C109_2') Or  IsNamedPolygon('C110_2') Or  IsNamedPolygon('12VP') Or  IsNamedPolygon('C113_2') Or  IsNamedPolygon('C107_1') Or  IsNamedPolygon('AC_N') Or  IsNamedPolygon('C107_1') Or  IsNamedPolygon('C109_1') Or  IsNamedPolygon('Earth') Or  IsNamedPolygon('F100_2') Or  IsNamedPolygon('AC_N') Or  IsNamedPolygon('C113_2') Or  IsNamedPolygon('Earth') Or  IsNamedPolygon('F100_2') Or  IsNamedPolygon('C107_1') Or  IsNamedPolygon('Earth') Or  IsNamedPolygon('F100_2') Or  IsNamedPolygon('-BRDG_N') Or  IsNamedPolygon('-BRDG_N') Or  IsNamedPolygon('-BRDG_N') Or  IsNamedPolygon('-BRDG_N') Or  IsNamedPolygon('-BRDG_N') Or  IsNamedPolygon('AC_L') Or  IsNamedPolygon('C109_1') Or  IsNamedPolygon('AC_N') Or  IsNamedPolygon('C109_1') Or  IsNamedPolygon('F100_2') Or  IsNamedPolygon('-BRDG_N') Or  IsNamedPolygon('AC_N') Or  IsNamedPolygon('C109_1') Or  IsNamedPolygon('C107_1') Or  IsNamedPolygon('Earth') Or  IsNamedPolygon('C109_1') Or  IsNamedPolygon('AC_N') Or  IsNamedPolygon('F100_2') Or  IsNamedPolygon('Earth') Or  IsNamedPolygon('Earth') Or  IsNamedPolygon('C107_1') Or  IsNamedPolygon('AC_N') Or  IsNamedPolygon('F100_2') Or  IsNamedPolygon('C109_1') Or  IsNamedPolygon('AC_N') Or  IsNamedPolygon('C107_1')] p6: connectstyle=Direct reliefconductorwidth=10 reliefentries=4 polygonreliefangle="90 Angle" airgapwidth=10
PolygonConnect PolygonConnect_20 [All vs IsNamedPolygon('12VP') Or  IsNamedPolygon('C110_2') Or  IsNamedPolygon('C110_2') Or  IsNamedPolygon('-BRDG_N') Or  IsNamedPolygon('C113_2') Or  IsNamedPolygon('-BRDG_N') Or  IsNamedPolygon('F100_2') Or  IsNamedPolygon('C113_2') Or  IsNamedPolygon('-BRDG_N') Or  IsNamedPolygon('AC_N') Or  IsNamedPolygon('C110_2') Or  IsNamedPolygon('C110_2') Or  IsNamedPolygon('C113_2') Or  IsNamedPolygon('AC_N') Or  IsNamedPolygon('AC_N') Or  IsNamedPolygon('C113_2') Or  IsNamedPolygon('AC_N') Or  IsNamedPolygon('F100_2') Or  IsNamedPolygon('C113_2') Or  IsNamedPolygon('-BRDG_N') Or  IsNamedPolygon('-BRDG_N') Or  IsNamedPolygon('F100_2') Or  IsNamedPolygon('F100_2') Or  IsNamedPolygon('AC_N') Or  IsNamedPolygon('C113_2') Or  IsNamedPolygon('F100_2') Or  IsNamedPolygon('F100_2') Or  IsNamedPolygon('AC_N') Or  IsNamedPolygon('AC_N') Or  IsNamedPolygon('-BRDG_N') Or  IsNamedPolygon('Earth') Or  IsNamedPolygon('C107_1') Or  IsNamedPolygon('Earth') Or  IsNamedPolygon('C107_1') Or  IsNamedPolygon('Earth') Or  IsNamedPolygon('C109_1') Or  IsNamedPolygon('C109_1') Or  IsNamedPolygon('C107_1') Or  IsNamedPolygon('C109_1') Or  IsNamedPolygon('C107_1') Or  IsNamedPolygon('C109_1') Or  IsNamedPolygon('C109_1') Or  IsNamedPolygon('Earth') Or  IsNamedPolygon('C107_1') Or  IsNamedPolygon('C107_1') Or  IsNamedPolygon('Earth') Or  IsNamedPolygon('C109_1') Or  IsNamedPolygon('C109_2') Or  IsNamedPolygon('C109_2') Or  IsNamedPolygon('C110_2') Or  IsNamedPolygon('C110_2') Or  IsNamedPolygon('C109_2') Or  IsNamedPolygon('C109_2') Or  IsNamedPolygon('5VS') Or  IsNamedPolygon('C109_2') Or  IsNamedPolygon('D106_1') Or  IsNamedPolygon('C109_2')] p7: connectstyle=Direct reliefconductorwidth=10 reliefentries=4 polygonreliefangle="90 Angle" airgapwidth=10
PolygonConnect PolygonConnect_19 [All vs IsNamedPolygon('C107_1') Or  IsNamedPolygon('C107_1') Or  IsNamedPolygon('C109_1') Or  IsNamedPolygon('C107_1') Or  IsNamedPolygon('C109_1') Or  IsNamedPolygon('C107_1') Or  IsNamedPolygon('F100_2') Or  IsNamedPolygon('C109_1') Or  IsNamedPolygon('C107_1') Or  IsNamedPolygon('C107_1') Or  IsNamedPolygon('C109_1') Or  IsNamedPolygon('C109_1') Or  IsNamedPolygon('C109_1') Or  IsNamedPolygon('12VP') Or  IsNamedPolygon('C109_2') Or  IsNamedPolygon('F100_2') Or  IsNamedPolygon('F100_2') Or  IsNamedPolygon('-BRDG_N') Or  IsNamedPolygon('AC_N') Or  IsNamedPolygon('AC_N') Or  IsNamedPolygon('F100_2') Or  IsNamedPolygon('AC_N') Or  IsNamedPolygon('C113_2') Or  IsNamedPolygon('C110_2') Or  IsNamedPolygon('AC_N') Or  IsNamedPolygon('C113_2') Or  IsNamedPolygon('C110_2') Or  IsNamedPolygon('5VS') Or  IsNamedPolygon('C109_2') Or  IsNamedPolygon('C113_2') Or  IsNamedPolygon('AC_N') Or  IsNamedPolygon('-BRDG_N') Or  IsNamedPolygon('F100_2') Or  IsNamedPolygon('C109_2') Or  IsNamedPolygon('-BRDG_N') Or  IsNamedPolygon('D106_1') Or  IsNamedPolygon('C110_2') Or  IsNamedPolygon('C113_2') Or  IsNamedPolygon('C109_2') Or  IsNamedPolygon('C110_2') Or  IsNamedPolygon('C109_2') Or  IsNamedPolygon('-BRDG_N') Or  IsNamedPolygon('C110_2') Or  IsNamedPolygon('AC_N') Or  IsNamedPolygon('C113_2') Or  IsNamedPolygon('F100_2') Or  IsNamedPolygon('C109_2') Or  IsNamedPolygon('C113_2') Or  IsNamedPolygon('-BRDG_N') Or  IsNamedPolygon('AC_N') Or  IsNamedPolygon('C110_2') Or  IsNamedPolygon('-BRDG_N')] p8: connectstyle=Direct reliefconductorwidth=10 reliefentries=4 polygonreliefangle="90 Angle" airgapwidth=10
PolygonConnect PolygonConnect_18 [All vs IsNamedPolygon('C109_2') Or  IsNamedPolygon('C109_2') Or  IsNamedPolygon('D106_1') Or  IsNamedPolygon('C109_2') Or  IsNamedPolygon('C110_2') Or  IsNamedPolygon('C110_2') Or  IsNamedPolygon('C109_2') Or  IsNamedPolygon('C109_2') Or  IsNamedPolygon('5VS') Or  IsNamedPolygon('C109_2') Or  IsNamedPolygon('F100_2') Or  IsNamedPolygon('AC_N') Or  IsNamedPolygon('AC_N') Or  IsNamedPolygon('-BRDG_N') Or  IsNamedPolygon('-BRDG_N') Or  IsNamedPolygon('C113_2') Or  IsNamedPolygon('-BRDG_N') Or  IsNamedPolygon('C110_2') Or  IsNamedPolygon('C113_2') Or  IsNamedPolygon('AC_N') Or  IsNamedPolygon('AC_N') Or  IsNamedPolygon('AC_N') Or  IsNamedPolygon('AC_N') Or  IsNamedPolygon('-BRDG_N') Or  IsNamedPolygon('C113_2') Or  IsNamedPolygon('C110_2') Or  IsNamedPolygon('F100_2') Or  IsNamedPolygon('C113_2') Or  IsNamedPolygon('AC_N') Or  IsNamedPolygon('F100_2') Or  IsNamedPolygon('C113_2') Or  IsNamedPolygon('C109_1') Or  IsNamedPolygon('F100_2') Or  IsNamedPolygon('C109_1') Or  IsNamedPolygon('-BRDG_N') Or  IsNamedPolygon('F100_2') Or  IsNamedPolygon('C113_2') Or  IsNamedPolygon('C110_2') Or  IsNamedPolygon('F100_2') Or  IsNamedPolygon('-BRDG_N') Or  IsNamedPolygon('C110_2') Or  IsNamedPolygon('C109_1') Or  IsNamedPolygon('C109_1') Or  IsNamedPolygon('C109_1') Or  IsNamedPolygon('C109_1') Or  IsNamedPolygon('12VP')] p9: connectstyle=Direct reliefconductorwidth=10 reliefentries=4 polygonreliefangle="90 Angle" airgapwidth=10
PolygonConnect PolygonConnect_17 [All vs IsNamedPolygon('AC_N') Or  IsNamedPolygon('-BRDG_N') Or  IsNamedPolygon('F100_2') Or  IsNamedPolygon('-BRDG_N') Or  IsNamedPolygon('-BRDG_N') Or  IsNamedPolygon('F100_2') Or  IsNamedPolygon('AC_N') Or  IsNamedPolygon('F100_2') Or  IsNamedPolygon('-BRDG_N') Or  IsNamedPolygon('F100_2') Or  IsNamedPolygon('AC_N') Or  IsNamedPolygon('F100_2') Or  IsNamedPolygon('-BRDG_N') Or  IsNamedPolygon('AC_N') Or  IsNamedPolygon('-BRDG_N') Or  IsNamedPolygon('F100_2') Or  IsNamedPolygon('C113_2') Or  IsNamedPolygon('D106_1') Or  IsNamedPolygon('C113_2') Or  IsNamedPolygon('AC_N') Or  IsNamedPolygon('C113_2') Or  IsNamedPolygon('C113_2') Or  IsNamedPolygon('C110_2') Or  IsNamedPolygon('C110_2') Or  IsNamedPolygon('C113_2') Or  IsNamedPolygon('5VS') Or  IsNamedPolygon('C109_2') Or  IsNamedPolygon('C109_2') Or  IsNamedPolygon('AC_N') Or  IsNamedPolygon('C110_2') Or  IsNamedPolygon('C113_2') Or  IsNamedPolygon('C109_2') Or  IsNamedPolygon('C110_2') Or  IsNamedPolygon('C109_2') Or  IsNamedPolygon('AC_N') Or  IsNamedPolygon('C109_2') Or  IsNamedPolygon('C110_2') Or  IsNamedPolygon('C109_2') Or  IsNamedPolygon('C110_2') Or  IsNamedPolygon('12VP')] p10: connectstyle=Direct reliefconductorwidth=10 reliefentries=4 polygonreliefangle="90 Angle" airgapwidth=10
PolygonConnect PolygonConnect_16 [All vs IsNamedPolygon('12VP') Or  IsNamedPolygon('AC_N') Or  IsNamedPolygon('C109_2') Or  IsNamedPolygon('AC_N') Or  IsNamedPolygon('AC_N') Or  IsNamedPolygon('AC_N') Or  IsNamedPolygon('C110_2') Or  IsNamedPolygon('C113_2') Or  IsNamedPolygon('C113_2') Or  IsNamedPolygon('C113_2') Or  IsNamedPolygon('C109_2') Or  IsNamedPolygon('C113_2') Or  IsNamedPolygon('5VS') Or  IsNamedPolygon('C110_2') Or  IsNamedPolygon('C110_2') Or  IsNamedPolygon('C109_2') Or  IsNamedPolygon('C109_2') Or  IsNamedPolygon('D106_1') Or  IsNamedPolygon('C110_2') Or  IsNamedPolygon('C110_2') Or  IsNamedPolygon('C113_2') Or  IsNamedPolygon('AC_N') Or  IsNamedPolygon('C109_2') Or  IsNamedPolygon('AC_N') Or  IsNamedPolygon('-BRDG_N') Or  IsNamedPolygon('C110_2') Or  IsNamedPolygon('-BRDG_N') Or  IsNamedPolygon('C109_2') Or  IsNamedPolygon('C113_2')] p11: connectstyle=Direct reliefconductorwidth=10 reliefentries=4 polygonreliefangle="90 Angle" airgapwidth=10
PolygonConnect PolygonConnect_15 [All vs IsNamedPolygon('12VP') Or  IsNamedPolygon('AC_N') Or  IsNamedPolygon('C113_2') Or  IsNamedPolygon('AC_N') Or  IsNamedPolygon('C110_2') Or  IsNamedPolygon('D106_1') Or  IsNamedPolygon('C110_2') Or  IsNamedPolygon('C113_2') Or  IsNamedPolygon('C109_2') Or  IsNamedPolygon('C113_2') Or  IsNamedPolygon('C109_2') Or  IsNamedPolygon('C113_2') Or  IsNamedPolygon('AC_N') Or  IsNamedPolygon('AC_N') Or  IsNamedPolygon('AC_N') Or  IsNamedPolygon('C109_2') Or  IsNamedPolygon('5VS') Or  IsNamedPolygon('C110_2') Or  IsNamedPolygon('C109_2') Or  IsNamedPolygon('C110_2') Or  IsNamedPolygon('C110_2') Or  IsNamedPolygon('C113_2') Or  IsNamedPolygon('C110_2') Or  IsNamedPolygon('C109_2') Or  IsNamedPolygon('C113_2') Or  IsNamedPolygon('C109_2') Or  IsNamedPolygon('AC_N')] p12: connectstyle=Direct reliefconductorwidth=10 reliefentries=4 polygonreliefangle="90 Angle" airgapwidth=10
PolygonConnect PolygonConnect_14 [All vs IsNamedPolygon('C110_2') Or  IsNamedPolygon('C110_2') Or  IsNamedPolygon('C109_2') Or  IsNamedPolygon('C113_2') Or  IsNamedPolygon('C113_2') Or  IsNamedPolygon('D106_1') Or  IsNamedPolygon('C110_2') Or  IsNamedPolygon('C113_2') Or  IsNamedPolygon('C110_2') Or  IsNamedPolygon('C109_2') Or  IsNamedPolygon('C109_2') Or  IsNamedPolygon('C109_2') Or  IsNamedPolygon('C113_2') Or  IsNamedPolygon('C113_2') Or  IsNamedPolygon('C110_2') Or  IsNamedPolygon('C110_2') Or  IsNamedPolygon('C113_2') Or  IsNamedPolygon('C109_2') Or  IsNamedPolygon('5VS') Or  IsNamedPolygon('C109_2') Or  IsNamedPolygon('12VP')] p13: connectstyle=Direct reliefconductorwidth=10 reliefentries=4 polygonreliefangle="90 Angle" airgapwidth=10
PolygonConnect PolygonConnect_13 [All vs IsNamedPolygon('C110_2') Or  IsNamedPolygon('C109_2') Or  IsNamedPolygon('D106_1') Or  IsNamedPolygon('C109_2') Or  IsNamedPolygon('C110_2') Or  IsNamedPolygon('C110_2') Or  IsNamedPolygon('C110_2') Or  IsNamedPolygon('C109_2') Or  IsNamedPolygon('C109_2') Or  IsNamedPolygon('C109_2') Or  IsNamedPolygon('C110_2') Or  IsNamedPolygon('C110_2') Or  IsNamedPolygon('C110_2') Or  IsNamedPolygon('5VS') Or  IsNamedPolygon('C109_2') Or  IsNamedPolygon('12VP')] p14: connectstyle=Direct reliefconductorwidth=10 reliefentries=4 polygonreliefangle="90 Angle" airgapwidth=10
PolygonConnect PolygonConnect_12 [All vs IsNamedPolygon('5VS') Or  IsNamedPolygon('C109_2') Or  IsNamedPolygon('D106_1') Or  IsNamedPolygon('C109_2') Or  IsNamedPolygon('C109_2') Or  IsNamedPolygon('C109_2') Or  IsNamedPolygon('C109_2') Or  IsNamedPolygon('C109_2') Or  IsNamedPolygon('12VP')] p15: connectstyle=Direct reliefconductorwidth=10 reliefentries=4 polygonreliefangle="90 Angle" airgapwidth=10
PolygonConnect PolygonConnect_11 [All vs IsNamedPolygon('D106_1') Or  IsNamedPolygon('12VP') Or  IsNamedPolygon('5VS')] p16: connectstyle=Direct reliefconductorwidth=10 reliefentries=4 polygonreliefangle="90 Angle" airgapwidth=10
PolygonConnect PolygonConnect_10 [All vs IsNamedPolygon('12VP') Or  IsNamedPolygon('D106_1')] p17: connectstyle=Direct reliefconductorwidth=10 reliefentries=4 polygonreliefangle="90 Angle" airgapwidth=10
PolygonConnect PolygonConnect_9 [All vs IsNamedPolygon('C11_1') Or  IsNamedPolygon('Vin') Or  IsNamedPolygon('Vin') Or  IsNamedPolygon('5V') Or  IsNamedPolygon('D6_2') Or  IsNamedPolygon('Q3_3') Or  IsNamedPolygon('GND2') Or  IsNamedPolygon('GND2') Or  IsNamedPolygon('GND') Or  IsNamedPolygon('Q3_4') Or  IsNamedPolygon('12V5') Or  IsNamedPolygon('GND') Or  IsNamedPolygon('12V5') Or  IsNamedPolygon('D3_1')] p18: connectstyle=Direct reliefconductorwidth=10 reliefentries=4 polygonreliefangle="90 Angle" airgapwidth=10
PolygonConnect PolygonConnect_8 [All vs IsNamedPolygon('C11_1') Or  IsNamedPolygon('Vin') Or  IsNamedPolygon('12V5') Or  IsNamedPolygon('Q3_3') Or  IsNamedPolygon('GND2') Or  IsNamedPolygon('GND2') Or  IsNamedPolygon('5V') Or  IsNamedPolygon('Q3_4') Or  IsNamedPolygon('12V5')] p19: connectstyle=Direct reliefconductorwidth=10 reliefentries=4 polygonreliefangle="90 Angle" airgapwidth=10
PolygonConnect PolygonConnect_7 [All vs IsNamedPolygon('GND2') Or  IsNamedPolygon('GND2') Or  IsNamedPolygon('5V') Or  IsNamedPolygon('12V5') Or  IsNamedPolygon('12V5') Or  IsNamedPolygon('C11_1')] p20: connectstyle=Direct reliefconductorwidth=10 reliefentries=4 polygonreliefangle="90 Angle" airgapwidth=10
PolygonConnect PolygonConnect_6 [All vs IsNamedPolygon('GND2') Or  IsNamedPolygon('SGND') Or  IsNamedPolygon('GND1') Or  IsNamedPolygon('C901_1') Or  IsNamedPolygon('SGND') Or  IsNamedPolygon('GND2') Or  IsNamedPolygon('GND1')] p21: connectstyle=Direct reliefconductorwidth=10 reliefentries=4 polygonreliefangle="90 Angle" airgapwidth=10
PolygonConnect PolygonConnect_5 [All vs IsNamedPolygon('GND1') Or  IsNamedPolygon('GND1')] p22: connectstyle=Direct reliefconductorwidth=10 reliefentries=4 polygonreliefangle="90 Angle" airgapwidth=10
PolygonConnect PolygonConnect_4 [All vs IsNamedPolygon('C21_1') Or  IsNamedPolygon('C5_1') Or  IsNamedPolygon('C12_2') Or  IsNamedPolygon('C2_2') Or  IsNamedPolygon('C13_1') Or  IsNamedPolygon('C28_1') Or  IsNamedPolygon('C6_1') Or  IsNamedPolygon('GND') Or  IsNamedPolygon('GND2') Or  IsNamedPolygon('C14_1') Or  IsNamedPolygon('C13_1') Or  IsNamedPolygon('Q1_3') Or  IsNamedPolygon('C14_1') Or  IsNamedPolygon('C5_1') Or  IsNamedPolygon('GND2') Or  IsNamedPolygon('C28_1') Or  IsNamedPolygon('D5_2') Or  IsNamedPolygon('D6_2') Or  IsNamedPolygon('D2_1') Or  IsNamedPolygon('C12_2') Or  IsNamedPolygon('D2_1') Or  IsNamedPolygon('C4_1') Or  IsNamedPolygon('C4_1') Or  IsNamedPolygon('C2_2') Or  IsNamedPolygon('GND') Or  IsNamedPolygon('C33_1') Or  IsNamedPolygon('C9_1')] p23: connectstyle=Direct reliefconductorwidth=10 reliefentries=4 polygonreliefangle="90 Angle" airgapwidth=10
PolygonConnect PolygonConnect_3 [All vs IsNamedPolygon('C28_1') Or  IsNamedPolygon('C12_2') Or  IsNamedPolygon('C28_1') Or  IsNamedPolygon('C9_1') Or  IsNamedPolygon('D5_2') Or  IsNamedPolygon('C12_2') Or  IsNamedPolygon('C2_2') Or  IsNamedPolygon('C14_1') Or  IsNamedPolygon('C4_1') Or  IsNamedPolygon('C14_1') Or  IsNamedPolygon('D6_2') Or  IsNamedPolygon('GND2') Or  IsNamedPolygon('Q1_3') Or  IsNamedPolygon('C5_1') Or  IsNamedPolygon('D2_1') Or  IsNamedPolygon('C4_1') Or  IsNamedPolygon('C13_1') Or  IsNamedPolygon('C5_1') Or  IsNamedPolygon('C13_1') Or  IsNamedPolygon('C33_1') Or  IsNamedPolygon('D2_1') Or  IsNamedPolygon('GND') Or  IsNamedPolygon('GND') Or  IsNamedPolygon('GND2') Or  IsNamedPolygon('C2_2') Or  IsNamedPolygon('C6_1') Or  IsNamedPolygon('C21_1')] p24: connectstyle=Direct reliefconductorwidth=10 reliefentries=4 polygonreliefangle="90 Angle" airgapwidth=10
PolygonConnect PolygonConnect_2 [All vs IsNamedPolygon('C21_1') Or  IsNamedPolygon('C4_1') Or  IsNamedPolygon('D5_2') Or  IsNamedPolygon('C5_1') Or  IsNamedPolygon('C14_1') Or  IsNamedPolygon('C13_1') Or  IsNamedPolygon('C4_1') Or  IsNamedPolygon('C33_1') Or  IsNamedPolygon('C12_2') Or  IsNamedPolygon('D2_1') Or  IsNamedPolygon('C2_2') Or  IsNamedPolygon('C28_1') Or  IsNamedPolygon('C12_2') Or  IsNamedPolygon('D2_1') Or  IsNamedPolygon('C5_1') Or  IsNamedPolygon('Q1_3') Or  IsNamedPolygon('GND') Or  IsNamedPolygon('D6_2') Or  IsNamedPolygon('C6_1') Or  IsNamedPolygon('C2_2') Or  IsNamedPolygon('C14_1') Or  IsNamedPolygon('C28_1') Or  IsNamedPolygon('C13_1') Or  IsNamedPolygon('C9_1') Or  IsNamedPolygon('GND')] p25: connectstyle=Direct reliefconductorwidth=10 reliefentries=4 polygonreliefangle="90 Angle" airgapwidth=10
PolygonConnect PolygonConnect_1 [All vs IsNamedPolygon('C28_1') Or  IsNamedPolygon('D5_2') Or  IsNamedPolygon('C5_1') Or  IsNamedPolygon('C5_1') Or  IsNamedPolygon('D2_1') Or  IsNamedPolygon('C21_1') Or  IsNamedPolygon('C9_1') Or  IsNamedPolygon('C4_1') Or  IsNamedPolygon('C14_1') Or  IsNamedPolygon('C28_1') Or  IsNamedPolygon('C6_1') Or  IsNamedPolygon('C12_2') Or  IsNamedPolygon('C33_1') Or  IsNamedPolygon('C4_1') Or  IsNamedPolygon('C13_1') Or  IsNamedPolygon('C12_2') Or  IsNamedPolygon('D6_2') Or  IsNamedPolygon('C2_2') Or  IsNamedPolygon('C14_1') Or  IsNamedPolygon('D2_1') Or  IsNamedPolygon('C2_2') Or  IsNamedPolygon('C13_1')] p26: connectstyle=Direct reliefconductorwidth=10 reliefentries=4 polygonreliefangle="90 Angle" airgapwidth=10
PolygonConnect [All] p27: connectstyle=Direct reliefconductorwidth=10 reliefentries=4 polygonreliefangle="90 Angle" airgapwidth=10
RoutingVias ThermalPadVias [IsVia and InAnyComponent] p1: holewidth=7.87 width=19.68 viastyle="Through Hole" minholewidth=7.87 minwidth=19.68 maxholewidth=12.99 maxwidth=23.62
RoutingVias [All] p2: holewidth=16 width=34 viastyle="Through Hole" minholewidth=7.87 minwidth=20 maxholewidth=40 maxwidth=65
SilkToBoardRegionClearance [Not ((IsComment or IsDesignator) And (Hide <> 'False')) and not InRegion(1000,500,4000,800)] p1:
SilkToSilkClearance SilkToSilkClearance_Pb-FreeLogo [(HasFootprint('Pb-Free_Overlay_Medium') OR HasFootprint('Pb-Free_Overlay_Small')) vs (HasFootprint('Pb-Free_Overlay_Medium') OR HasFootprint('Pb-Free_Overlay_Small'))] p1: silktosilkclearance=0
SilkToSilkClearance [All] p2: silktosilkclearance=1
SilkToSolderMaskClearance "Silk to Solder Mask Opening" [All] p1: minsilkscreentomaskgap=1 clearancetoexposedcopper=FALSE
SolderMaskExpansion [All] p1: expansion=1.97
Width [All] p1: maxlimit=100 minlimit=6 preferedwidth=10 checkconnectedcopper=TRUE
14 further rules are at their usual default settings.

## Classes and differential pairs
component class FiducialMark: FID1 FID2 FID3
component class EVM_Hardware1: !PCB FID1 FID2 FID3 Logo1 Logo3 LOGO4
net class MD: NetC1_2 NetC3_2 NetC5_2 NetC7_2 NetC9_2 NetC11_2 NetC13_2 NetC15_2 NetC17_2 NetC19_2 NetC21_2 NetC23_2 NetL100_4 NetL101_4 NetL102_4 PFC_1H_G PFC_1H_S PFC_2H_G PFC_2H_S PFC_3H_G PFC_3H_S
component class PowerBoard_Control: C600 C601 C602 C603 C604 C605 C606 C607 C608 C609 C610 C611 C612 C613 C614 C615 C616 C617 C618 J600 J602 J603 R600 R601 R602 R603 R604 R605 R606 R607 R608 R609 R610 R611 R612 R613 R614 R615 R616 R617 R618 R620 R621 R624 R625 R626 R630 R631 R632 R633 R634 R635 R636 R640 R641 R642 R643 R644 R645 R646 R? U203 U600 U601 U602
net class HV: AC_L AC_N HVBUS NetC36_2 NetC107_1 NetC109_1 NetC109_2 NetC110_2 NetC113_2 NetD2_1 NetD2_2 NetD100_1 NetD104_1 NetF100_2 NetL100_2 NetL101_2 NetL102_2 PFC_4H_G PFC_4H_S
component class PowerBoard: !PCB100 C1 C2 C3 C4 C5 C6 C7 C8 C9 C10 C11 C12 C13 C14 C15 C16 C17 C18 C19 C20 C21 C22 C23 C24 C27 C28 C29 C30 C31 C32 C33 C34 C35 C36 C37 C38 C39 C40 C41 C42 C107 C108 C109 C110 C111 C112 C113 C114 C115 C116 C118 C119 C120 C121 C122 C123 C124 C125 C127 C128 C129 C130 C131 C132 C133 C134 D1 D2 D3 D100 D102 D104 D105 D106 F100 J0 K1 L1 L100 L101 L102 L103 L104 P1 P2 P3 P4 Q1 Q2 Q3 Q4 Q5 Q6 Q7 Q8 Q9 Q10 Q11 Q12 R1 R2 R3 R4 R5 R6 R7 R8 R9 R10 R11 R12 R13 R14 R15 R16 R17 R18 R19 R20 R21 R22 R23 R24 R25 R35 R36 R37 R38 R39 R40 R41 R42 R43 R44 R45 R100 R101 R102 R105 R106 R107 R108 R109 R110 R111 R112 R113 R116 R117 R118 R119 R120 R121 R122 R123 R124 R125 RT100 RT101 RV100 T1 TP100 TP101 TP102 TP103 U1 U2 U100 U101 U102 U103 U104
net class MV: NetR101_2 NetR119_1 NetR602_1
net class EARTH: EARTH0

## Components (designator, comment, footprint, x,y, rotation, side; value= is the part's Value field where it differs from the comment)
C1 "350BXW150MEFR14.5X45" BXW_1450x4500 4500,1335 r0 top value=150uF
C2 "350BXW150MEFR14.5X45" BXW_1450x4500 5095,1335 r0 top value=150uF
C3 "350BXW150MEFR14.5X45" BXW_1450x4500 5690,1335 r0 top value=150uF
C4 "350BXW150MEFR14.5X45" BXW_1450x4500 6285,1335 r0 top value=150uF
C5 "350BXW150MEFR14.5X45" BXW_1450x4500 6880,1335 r0 top value=150uF
C6 "350BXW150MEFR14.5X45" BXW_1450x4500 7475,1335 r0 top value=150uF
C7 "350BXW150MEFR14.5X45" BXW_1450x4500 8070,1335 r0 top value=150uF
C8 "350BXW150MEFR14.5X45" BXW_1450x4500 8665,1335 r0 top value=150uF
C9 "350BXW150MEFR14.5X45" BXW_1450x4500 8963,815 r180 top value=150uF
C10 "350BXW150MEFR14.5X45" BXW_1450x4500 8368,815 r180 top value=150uF
C11 "350BXW150MEFR14.5X45" BXW_1450x4500 7773,815 r180 top value=150uF
C12 "350BXW150MEFR14.5X45" BXW_1450x4500 7178,815 r180 top value=150uF
C13 "350BXW150MEFR14.5X45" BXW_1450x4500 6583,815 r180 top value=150uF
C14 "350BXW150MEFR14.5X45" BXW_1450x4500 5988,815 r180 top value=150uF
C15 "350BXW150MEFR14.5X45" BXW_1450x4500 5393,815 r180 top value=150uF
C16 "350BXW150MEFR14.5X45" BXW_1450x4500 4798,815 r180 top value=150uF
C17 "350BXW150MEFR14.5X45" BXW_1450x4500 4500,295 r0 top value=150uF
C18 "350BXW150MEFR14.5X45" BXW_1450x4500 5095,295 r0 top value=150uF
C19 "350BXW150MEFR14.5X45" BXW_1450x4500 5690,295 r0 top value=150uF
C20 "350BXW150MEFR14.5X45" BXW_1450x4500 6285,295 r0 top value=150uF
C21 "350BXW150MEFR14.5X45" BXW_1450x4500 6880,295 r0 top value=150uF
C22 "350BXW150MEFR14.5X45" BXW_1450x4500 7475,295 r0 top value=150uF
C23 "350BXW150MEFR14.5X45" BXW_1450x4500 8070,295 r0 top value=150uF
C24 "350BXW150MEFR14.5X45" BXW_1450x4500 8665,295 r0 top value=150uF
C27 "VJ1812Y473KXEAT5Z" 1812 4370,940 r0 top value=0.1uF
C28 "VJ1812Y473KXEAT5Z" 1812 4370,780 r0 top value=0.1uF
C29 "VJ1812Y473KXEAT5Z" 1812 4740,2510 r90 bottom value=0.1uF
C30 "VJ1812Y473KXEAT5Z" 1812 4900,2510 r90 bottom value=0.1uF
C31 "VJ1812Y473KXEAT5Z" 1812 6340,2520 r90 bottom value=0.1uF
C32 "VJ1812Y473KXEAT5Z" 1812 6500,2520 r90 bottom value=0.1uF
C33 "VJ1812Y473KXEAT5Z" 1812 7970,2520 r90 bottom value=0.1uF
C34 "VJ1812Y473KXEAT5Z" 1812 8130,2520 r90 bottom value=0.1uF
C35 "GRM31CR71E106KA12L" 1206_180 630,1670 r270 bottom value=10uF
C36 "C2012X7R2E102K085AA" 0805_HV 1070,1840 r0 bottom value=1000pF
C37 "06035A680JAT2A" 0603 550,1590 r270 bottom value=68pF
C38 "GRM185R60J105KE26D" 0603 1610,860 r0 bottom value=1uF
C39 "10TPE220ML" 7343-30 1611.5,980 r0 bottom value=220uF
C40 "10TPE220ML" 7343-30 1610,1190 r0 bottom value=220uF
C41 "GRM185R60J105KE26D" 0603 1740,1320 r0 bottom value=1uF
C42 "10TPE220ML" 7343-30 1650,1450 r0 bottom value=220uF
C107 "DE6E3KJ222MN3A" E_900x700x900 1940,2860 r270 bottom value=2200pF
C108 "DE6E3KJ222MN3A" E_900x700x900 2910,2860 r90 bottom value=2200pF
C109 "890324026034" WCAP-FTX2_2600x1500x2500 730,2660 r270 top value=2.2uF
C110 "890324026034" WCAP-FTX2_2600x1500x2500 2170,2660 r270 top value=2.2uF
C111 "GRM155R70J104KA01D" 0402 4660,3060 r0 bottom value=0.1uF
C112 "DE6E3KJ222MN3A" E_900x700x900 1940,2490 r270 bottom value=2200pF
C113 "DE6E3KJ222MN3A" E_900x700x900 2910,2490 r270 bottom value=2200pF
C114 "890324026034" WCAP-FTX2_2600x1500x2500 3610,2640 r270 top value=2.2uF
C115 "GRM185R60J105KE26D" 0603 4670,3000 r0 bottom value=1uF
C116 "06035A102KAT2A" 0603 4640,3150 r90 bottom value=1000pF
C118 "GRM155R70J104KA01D" 0402 3270,190 r0 top value=0.1uF
C119 "GRM185R60J105KE26D" 0603 3280,130 r0 top value=1uF
C120 "GRM188R71C102KA01D" 0603 2500,1080 r0 bottom value=1000pF
C121 "GRM155R70J104KA01D" 0402 6450,3060 r0 bottom value=0.1uF
C122 "0805YD106KAT2A" 0805_HV 2800,590 r0 bottom value=10uF
C123 "GRM185R60J105KE26D" 0603 6460,3000 r0 bottom value=1uF
C124 "GRM155R70J104KA01D" 0402 3390,210 r270 top value=0.1uF
C125 "06035A102KAT2A" 0603 6430,3150 r90 bottom value=1000pF
C127 "GRM155R60J102KA01D" 0402 3080,210 r270 top value=1000pF
C128 "GRM155R60J102KA01D" 0402 3020,210 r270 top value=1000pF
C129 "GRM155R70J223KA01D" 0402 3140,210 r90 top value=0.022uF
C130 "GRM155R70J104KA01D" 0402 8230,3060 r0 bottom value=0.1uF
C131 "GRM155R70J104KA01D" 0402 2960,210 r90 top value=0.1uF
C132 "GRM185R60J105KE26D" 0603 8240,3000 r0 bottom value=1uF
C133 "GRM155R70J104KA01D" 0402 2830,370 r0 top value=0.1uF
C134 "06035A102KAT2A" 0603 8200,3150 r90 bottom value=1000pF
C600 "C1608X7R1E105K080AB" 0603 2230,700 r270 bottom value=1uF
C601 "GRM155R70J103KA01D" 0402 2140,380 r90 top value=0.01uF
C602 "GCM155R71C104KA55D" 0402 2290,580 r270 bottom value=0.1uF
C603 "GRM155R60J104KA01D" 0402 2270,110 r90 bottom value=0.1uF
C604 "GRM155R70J103KA01D" 0402 1990,380 r90 top value=0.01uF
C605 "C1608X7R1E105K080AB" 0603 1810,720 r180 bottom value=1uF
C606 "GRM1555C1H471JA01D" 0402 1940,150 r180 bottom value=470pF
C607 "GRM155R70J103KA01D" 0402 1940,380 r90 top value=0.01uF
C608 "GRM155R60J472KA01D" 0402 2290,380 r90 bottom value=0.047uF
C609 "GRM1555C1H471JA01D" 0402 2040,390 r90 bottom value=470pF
C610 "GRM1555C1H471JA01D" 0402 2030,190 r90 bottom value=470pF
C611 "GRM155R70J103KA01D" 0402 1006.35,349.84 r180 top value=0.01uF
C612 "GRM155R70J103KA01D" 0402 890,400 r180 top value=0.01uF
C613 "GRM155R70J103KA01D" 0402 783.62,350 r0 top value=0.01uF
C614 "GRM155R70J104KA01D" 0402 890,940 r90 top value=0.1uF
C615 "C1608X7R1E105K080AB" 0603 580,1200 r90 top value=1uF
C616 "C1608X7R1E105K080AB" 0603 170,1190 r90 bottom value=1uF
C617 "GRM155R70J103KA01D" 0402 1230,380 r270 top value=0.01uF
C618 "GRM155R70J103KA01D" 0402 1028,361.65 r180 bottom value=0.01uF
D1 "ES1D-13-F" SMA 230,1740 r270 bottom value=200V
D2 "CGRM4007-G" SOD-123 880,1730 r180 top value=1.7V
D3 "PDS5100-13" POWERDI5 1240,990 r0 bottom value=100V
D100 "US1K-13-F" SMA 3020,1558.5 r90 bottom value=800V
D102 "GBJ2510-F" GBJ 3770,1950 r180 top value=1000V
D104 "US1K-13-F" SMA 2160,1350 r0 bottom value=800V
D105 "MMSZ4689T1G" SOD-123 2690,1020 r90 bottom value=5.1V
D106 "BAT165E6327HTSA1" SOD-323 2780,1040 r90 bottom value=40V
F100 "0324040.MXP" FUSE_0325_Vertical 280,2870 r270 top
FID1 "Fiducial" Fiducial10-20 8990,110 r90 top
FID2 "Fiducial" Fiducial10-20 4310,2230 r90 top
FID3 "Fiducial" Fiducial10-20 4150,2230 r90 top
J0 "Socket" PIN1 2210,2680 r90 bottom
J600 "HSEC8-160-01-L-DV-A-BL" controlCARD-120HSEC 1440,160 r180 top
J602 "DF59-3S-2V(51)" Hirose_DF59-3S-2V_51 -10,690 r270 top
J603 "DF59-3S-2V(51)" Hirose_DF59-3S-2V_51 -10,1070 r270 top
K1 "T90S1D12-5" Relay_T90S1 2610,1040 r0 top
L1 "MMZ1608R150ATA00" 0603 1370,1150 r90 bottom value="15 ohm"
L100 "G184014LF" G184014LF#1 4810,2840 r90 top value=260uH
L101 "G184014LF" G184014LF#2 6590,2840 r90 top value=260uH
L102 "G184014LF" G184014LF#2 8370,2840 r90 top value=260uH
L103 "7448052303" WE-CMBNC_XL 1450,2620 r0 top value=2.5mH
L104 "7448052303" WE-CMBNC_XL 2890,2682.83 r0 top value=2.5mH
Logo3 "Pb-Free Symbol" Pb-Free_Overlay_Small 4160,2100 r90 top
LOGO4 "DANGER HIGH VOLTAGE" IEC_HighVoltage_Small 9115.79,375.79 r0 top
P1 "driver" Driver 4770,1890 r0 top
P2 "driver" Driver 6370,1890 r0 top
P3 "driver" Driver 7970,1890 r0 top
P4 "driver" Driver 3530,1280 r270 top
Q1 "C3M0065100K" TO-247-4 4930,2230 r0 bottom value=1000V
Q2 "C3M0065100K" TO-247-4 5730,2230 r0 bottom value=1000V
Q3 "C3M0065100K" TO-247-4 6530,2230 r0 bottom value=1000V
Q4 "C3M0065100K" TO-247-4 7330,2230 r0 bottom value=1000V
Q5 "C3M0065100K" TO-247-4 8130,2230 r0 bottom value=1000V
Q6 "C3M0065100K" TO-247-4 8930,2230 r0 bottom value=1000V
Q7 "C2M0025120D" TO-247 4100,1120 r270 bottom value=1200V
Q8 "C2M0025120D" TO-247 4100,340 r270 bottom value=1200V
Q9 "C2M0025120D" TO-247 3920,1120 r90 bottom value=1200V
Q10 "C2M0025120D" TO-247 3920,340 r90 bottom value=1200V
Q11 "STD2NK100Z" DPAK 471.52,1625 r0 top value=1000V
Q12 "ZXMN7A11GTA" SOT-223 2490,880 r270 bottom value=70V
R1 "CRCW12061M00FKEA" 1206 4500,1330 r180 bottom value=1.00Meg
R2 "CRCW12061M00FKEA" 1206 5100,1330 r180 bottom value=1.00Meg
R3 "CRCW12061M00FKEA" 1206 5690,1330 r180 bottom value=1.00Meg
R4 "CRCW12061M00FKEA" 1206 6290,1330 r180 bottom value=1.00Meg
R5 "CRCW12061M00FKEA" 1206 6880,1330 r180 bottom value=1.00Meg
R6 "CRCW12061M00FKEA" 1206 7480,1330 r180 bottom value=1.00Meg
R7 "CRCW12061M00FKEA" 1206 8070,1330 r180 bottom value=1.00Meg
R8 "CRCW12061M00FKEA" 1206 8670,1330 r180 bottom value=1.00Meg
R9 "CRCW12061M00FKEA" 1206 8960,810 r0 bottom value=1.00Meg
R10 "CRCW12061M00FKEA" 1206 8370,810 r0 bottom value=1.00Meg
R11 "CRCW12061M00FKEA" 1206 7770,810 r0 bottom value=1.00Meg
R12 "CRCW12061M00FKEA" 1206 7180,810 r0 bottom value=1.00Meg
R13 "CRCW12061M00FKEA" 1206 6580,810 r0 bottom value=1.00Meg
R14 "CRCW12061M00FKEA" 1206 5990,810 r0 bottom value=1.00Meg
R15 "CRCW12061M00FKEA" 1206 5390,810 r0 bottom value=1.00Meg
R16 "CRCW12061M00FKEA" 1206 4800,810 r0 bottom value=1.00Meg
R17 "CRCW12061M00FKEA" 1206 4500,290 r180 bottom value=1.00Meg
R18 "CRCW12061M00FKEA" 1206 5100,290 r180 bottom value=1.00Meg
R19 "CRCW12061M00FKEA" 1206 5690,300 r180 bottom value=1.00Meg
R20 "CRCW12061M00FKEA" 1206 6280,290 r180 bottom value=1.00Meg
R21 "CRCW12061M00FKEA" 1206 6880,290 r180 bottom value=1.00Meg
R22 "CRCW12061M00FKEA" 1206 7470,290 r180 bottom value=1.00Meg
R23 "CRCW12061M00FKEA" 1206 8070,290 r180 bottom value=1.00Meg
R24 "CRCW12061M00FKEA" 1206 8670,290 r180 bottom value=1.00Meg
R25 "CRCW060310K0FKEA" 0603 320,1870 r0 top value=10.0k
R35 "CRCW060380K6FKEA" 0603 650,1886.26 r0 top value=80.6k
R36 "CRCW060328K0FKEA" 0603 650,1820 r0 top value=28.0k
R37 "RC0603FR-0720RL" 0603 200,1570 r0 bottom value=20.0
R38 "CRCW12062M00JNEA" 1206 890,1840 r0 bottom value=2.0Meg
R39 "CRCW12062M00JNEA" 1206 690,1830 r0 bottom value=2.0Meg
R40 "RC1206FR-07300KL" 1206 1090,1740 r180 bottom value=300k
R41 "ERJ-6GEYJ201V" 0805_HV 1100,1734.57 r0 top value=200
R42 "CRCW06031K00FKEA" 0603 500,1690 r180 bottom value=1.00k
